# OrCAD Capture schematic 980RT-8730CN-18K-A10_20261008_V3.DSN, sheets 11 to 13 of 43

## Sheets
11 P0031_S3_DUT1: size Custom
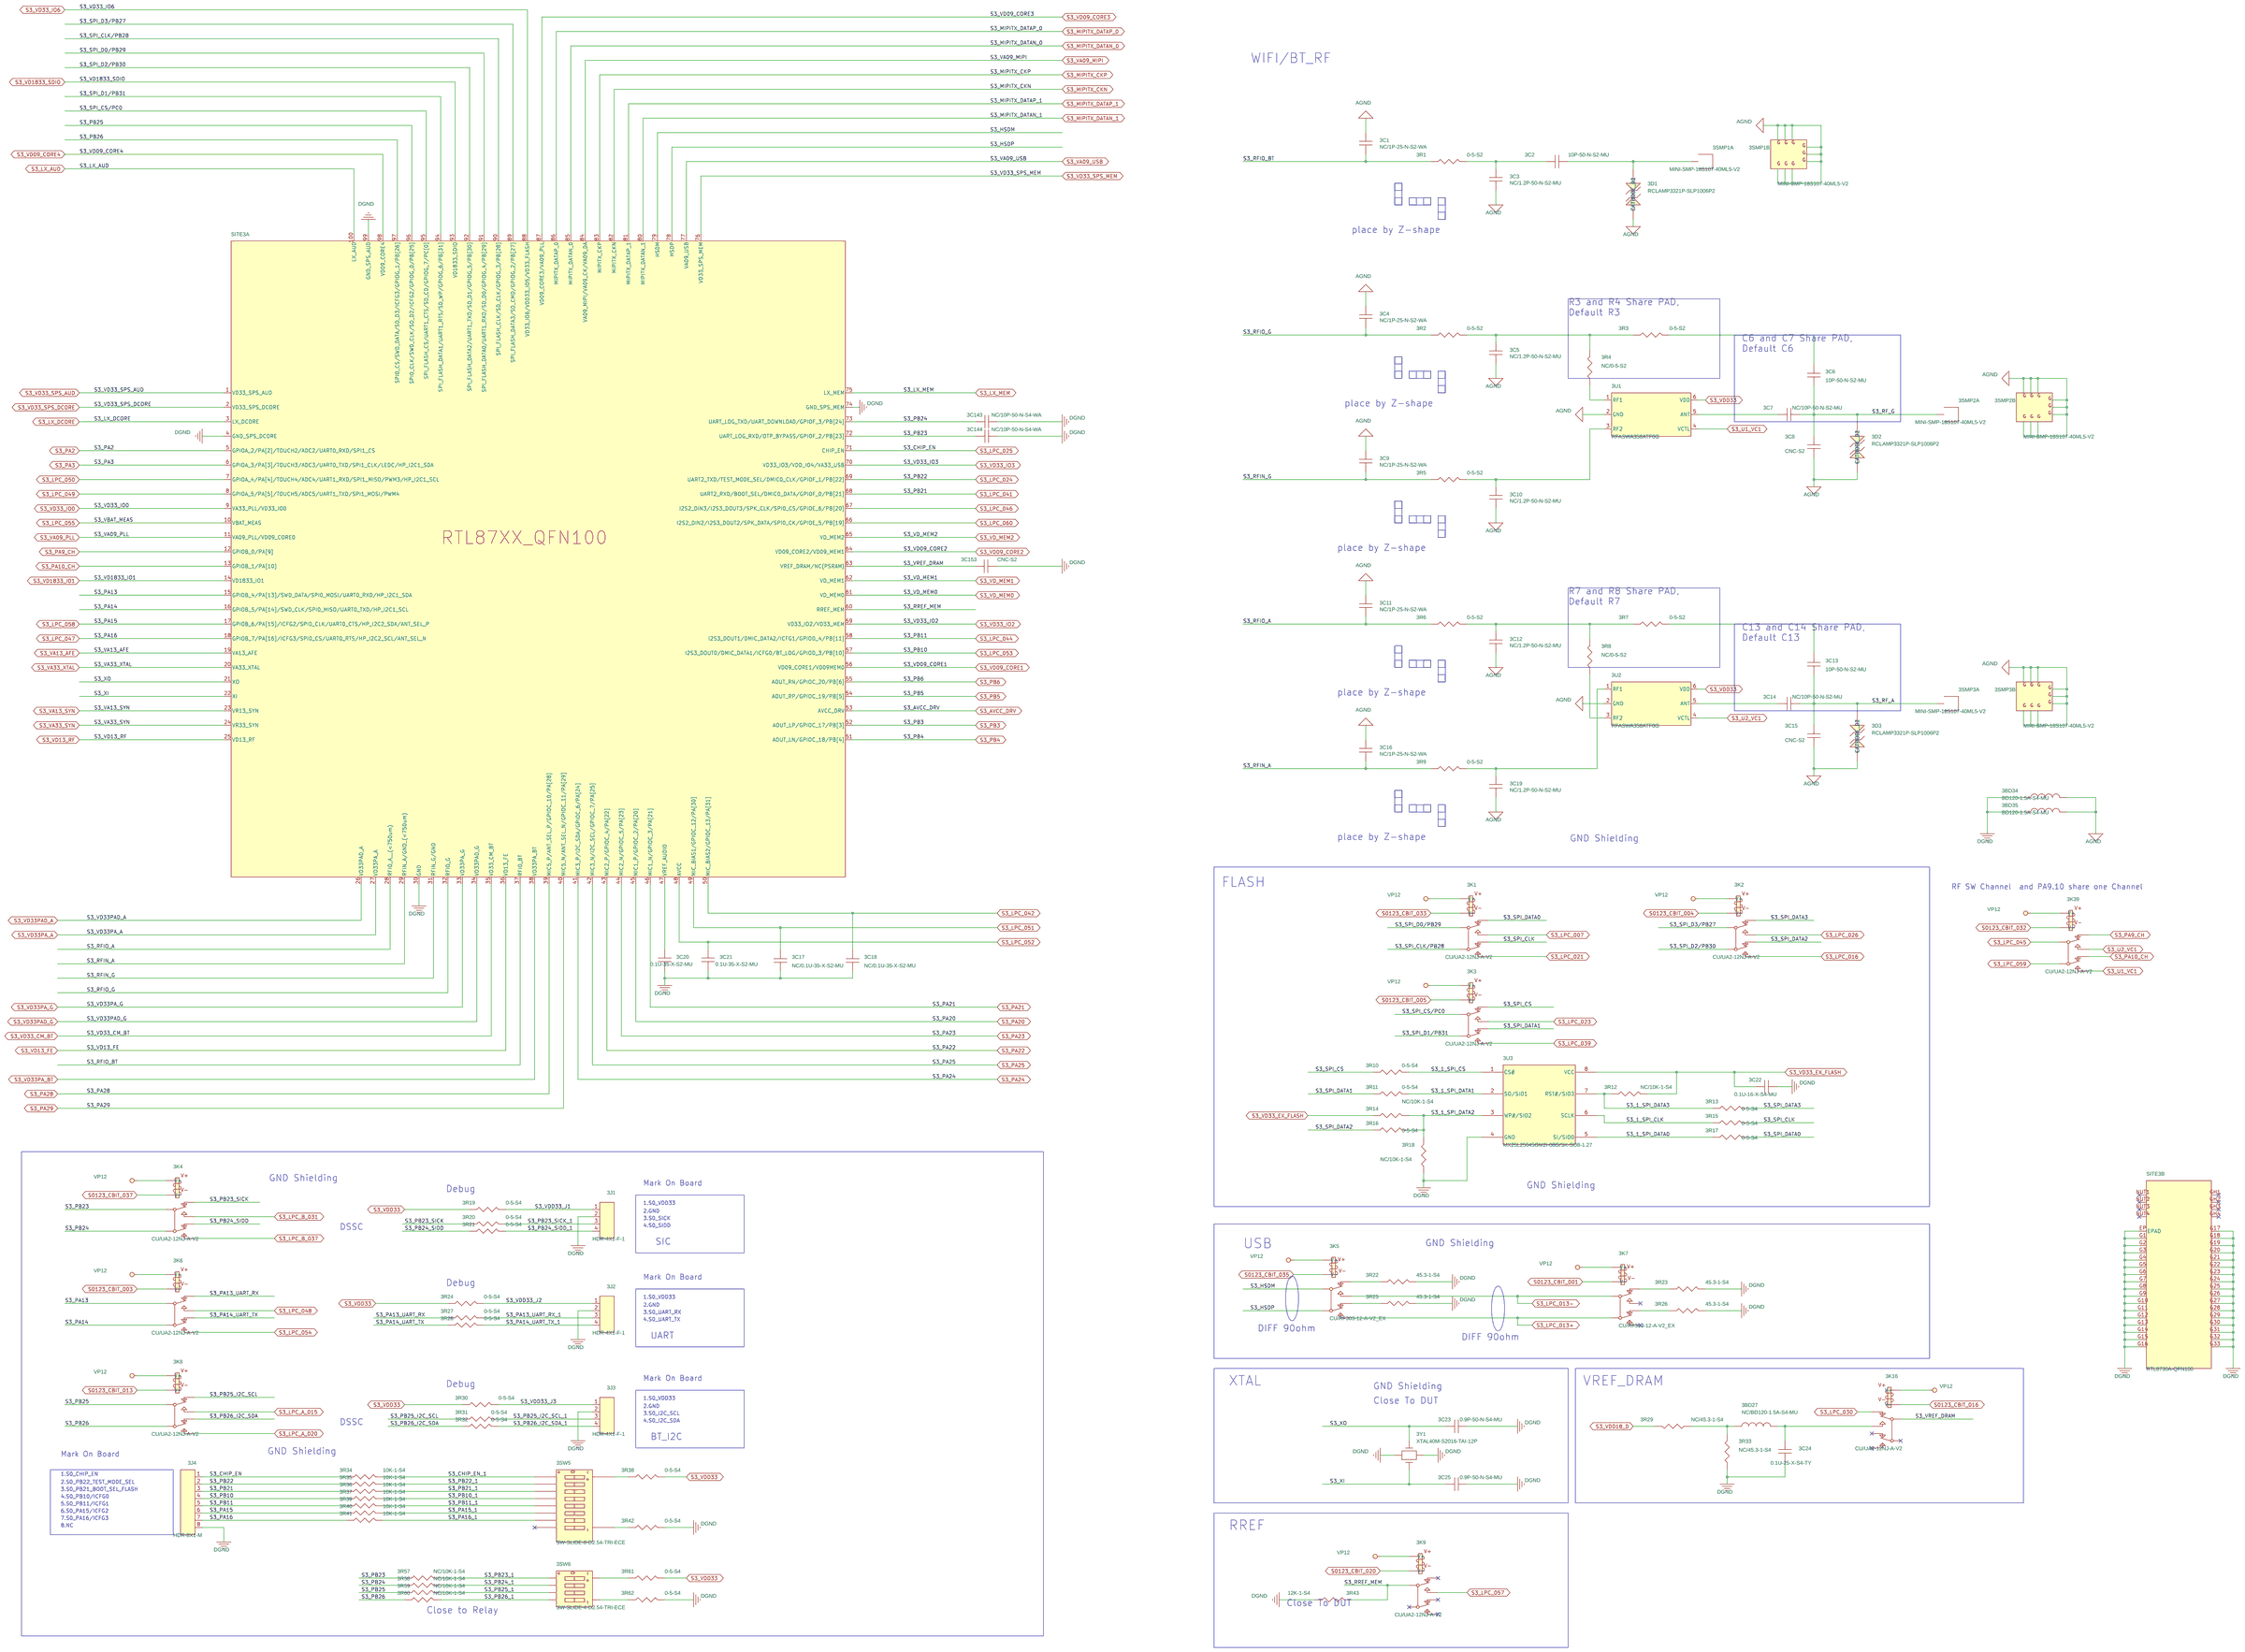
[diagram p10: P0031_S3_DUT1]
12 P0032_S3_Function-test: size A3
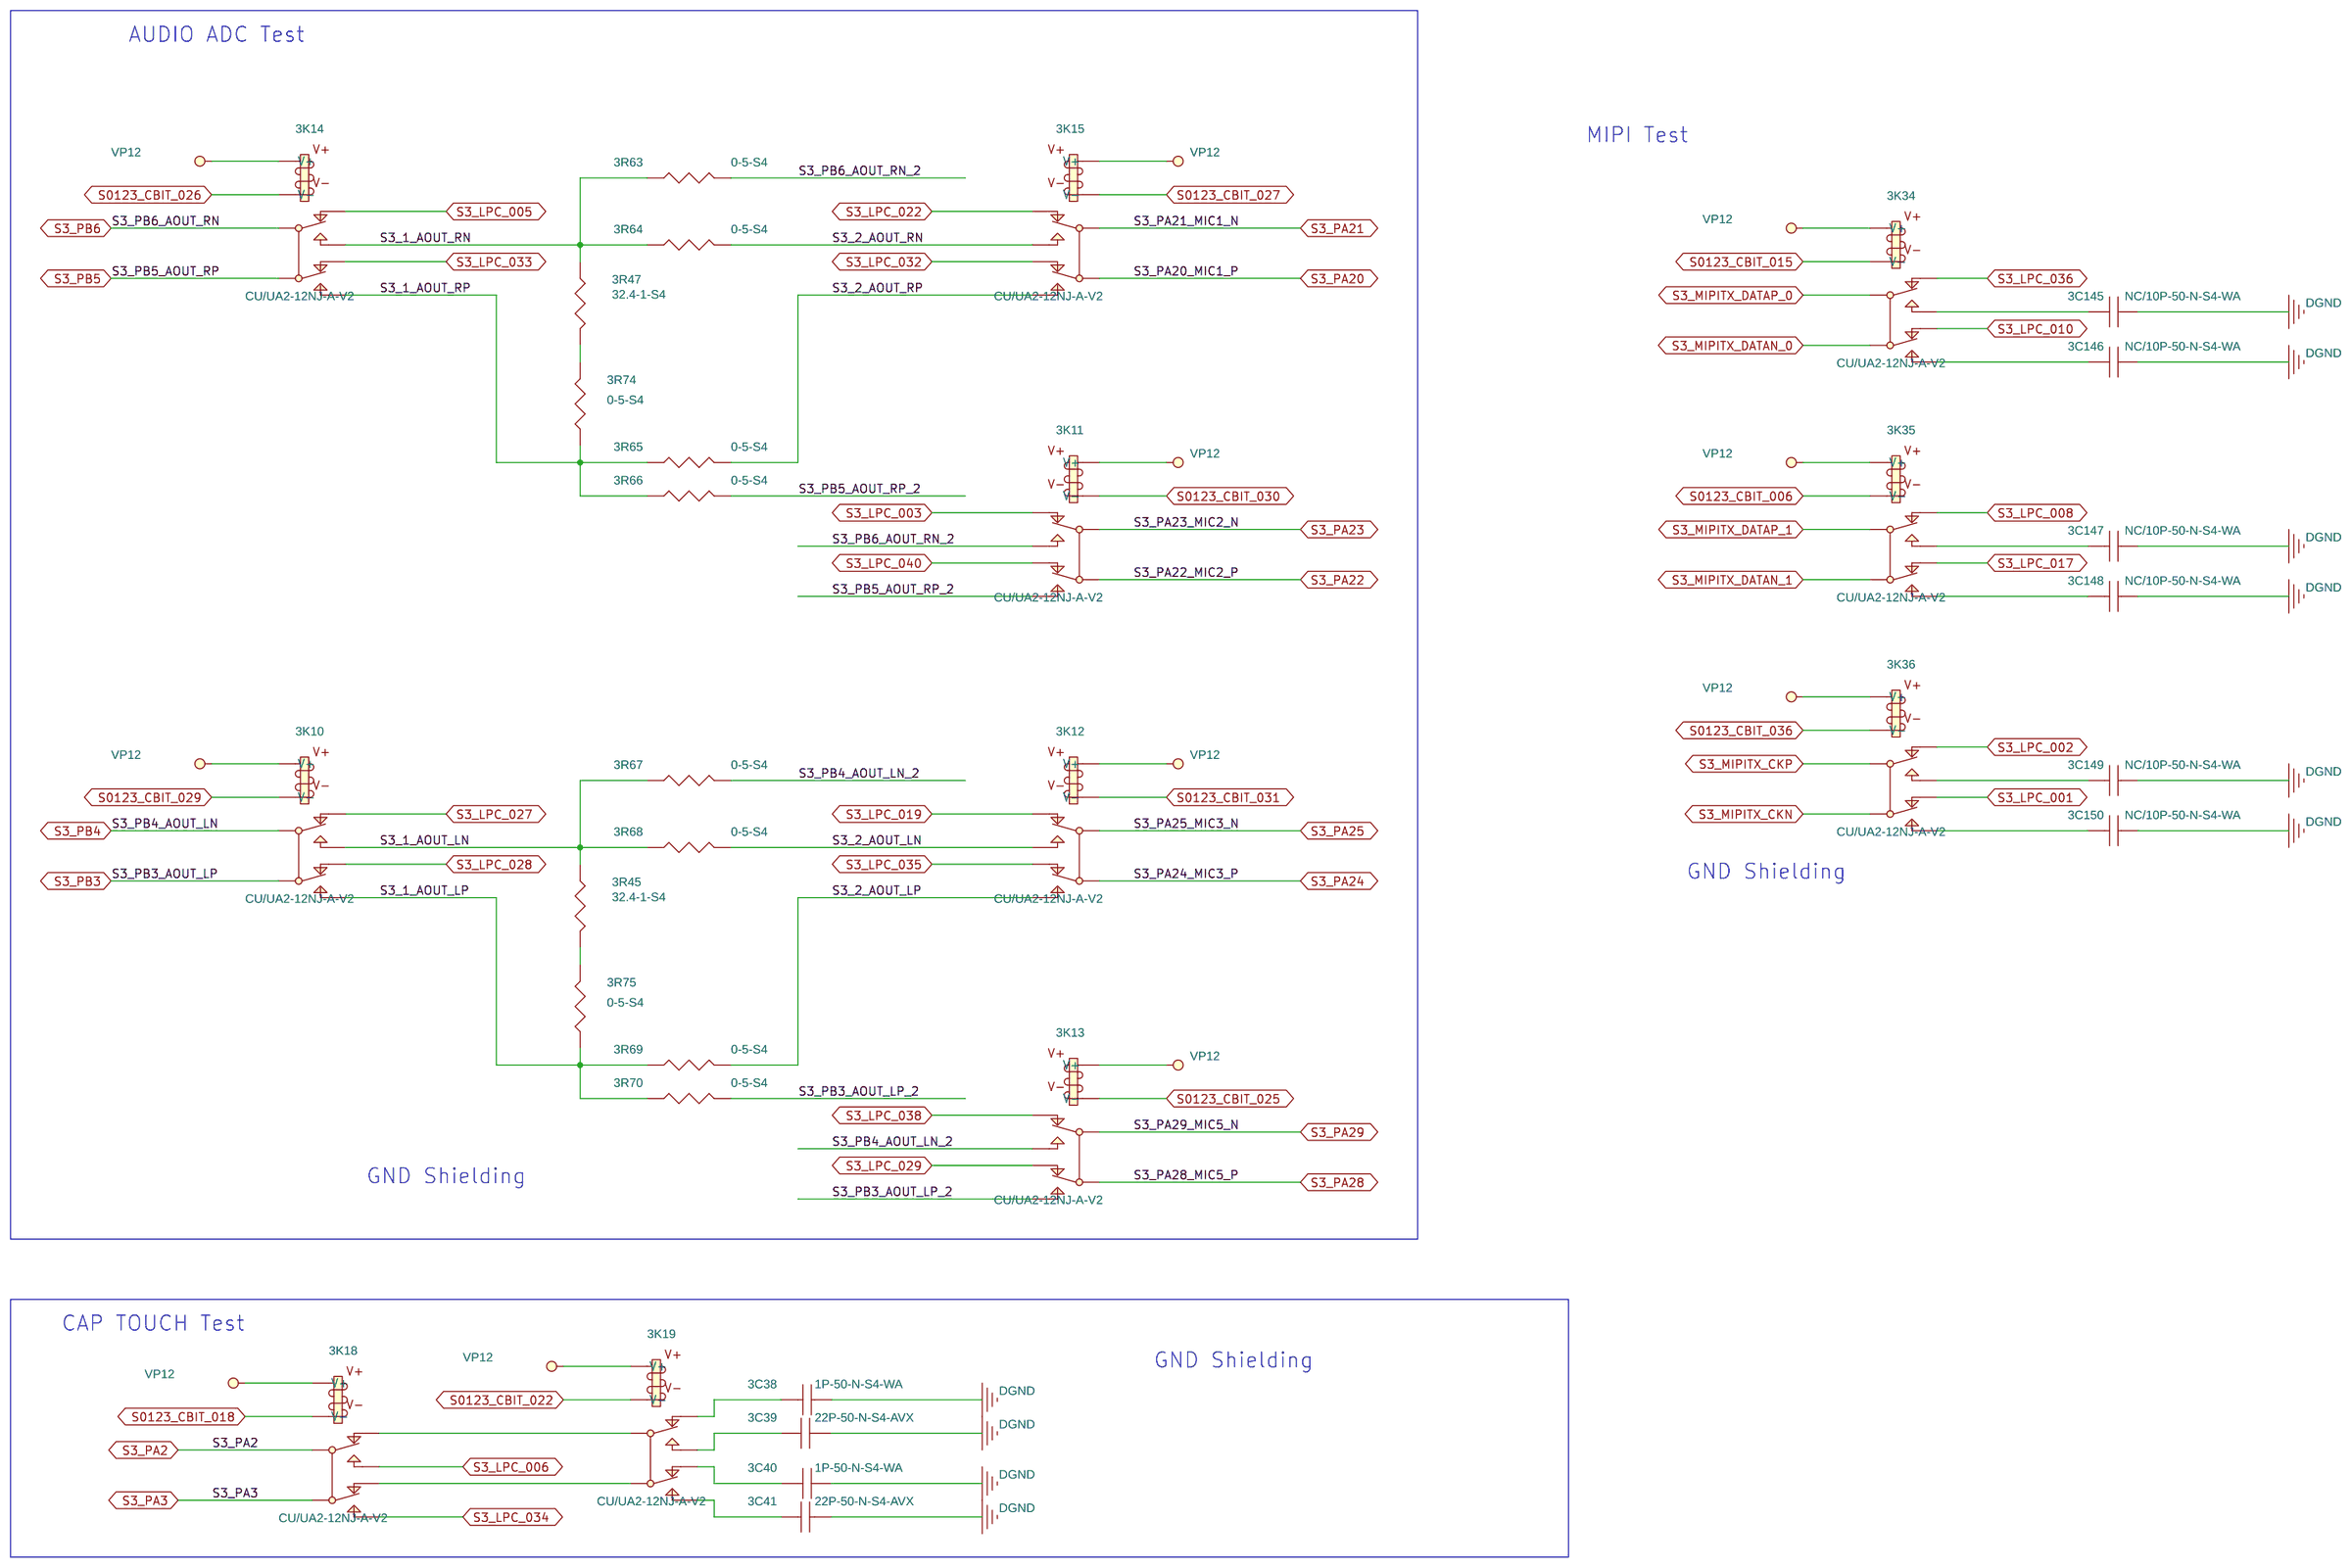
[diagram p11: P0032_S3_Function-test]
13 P0033_S3_Power: size A1
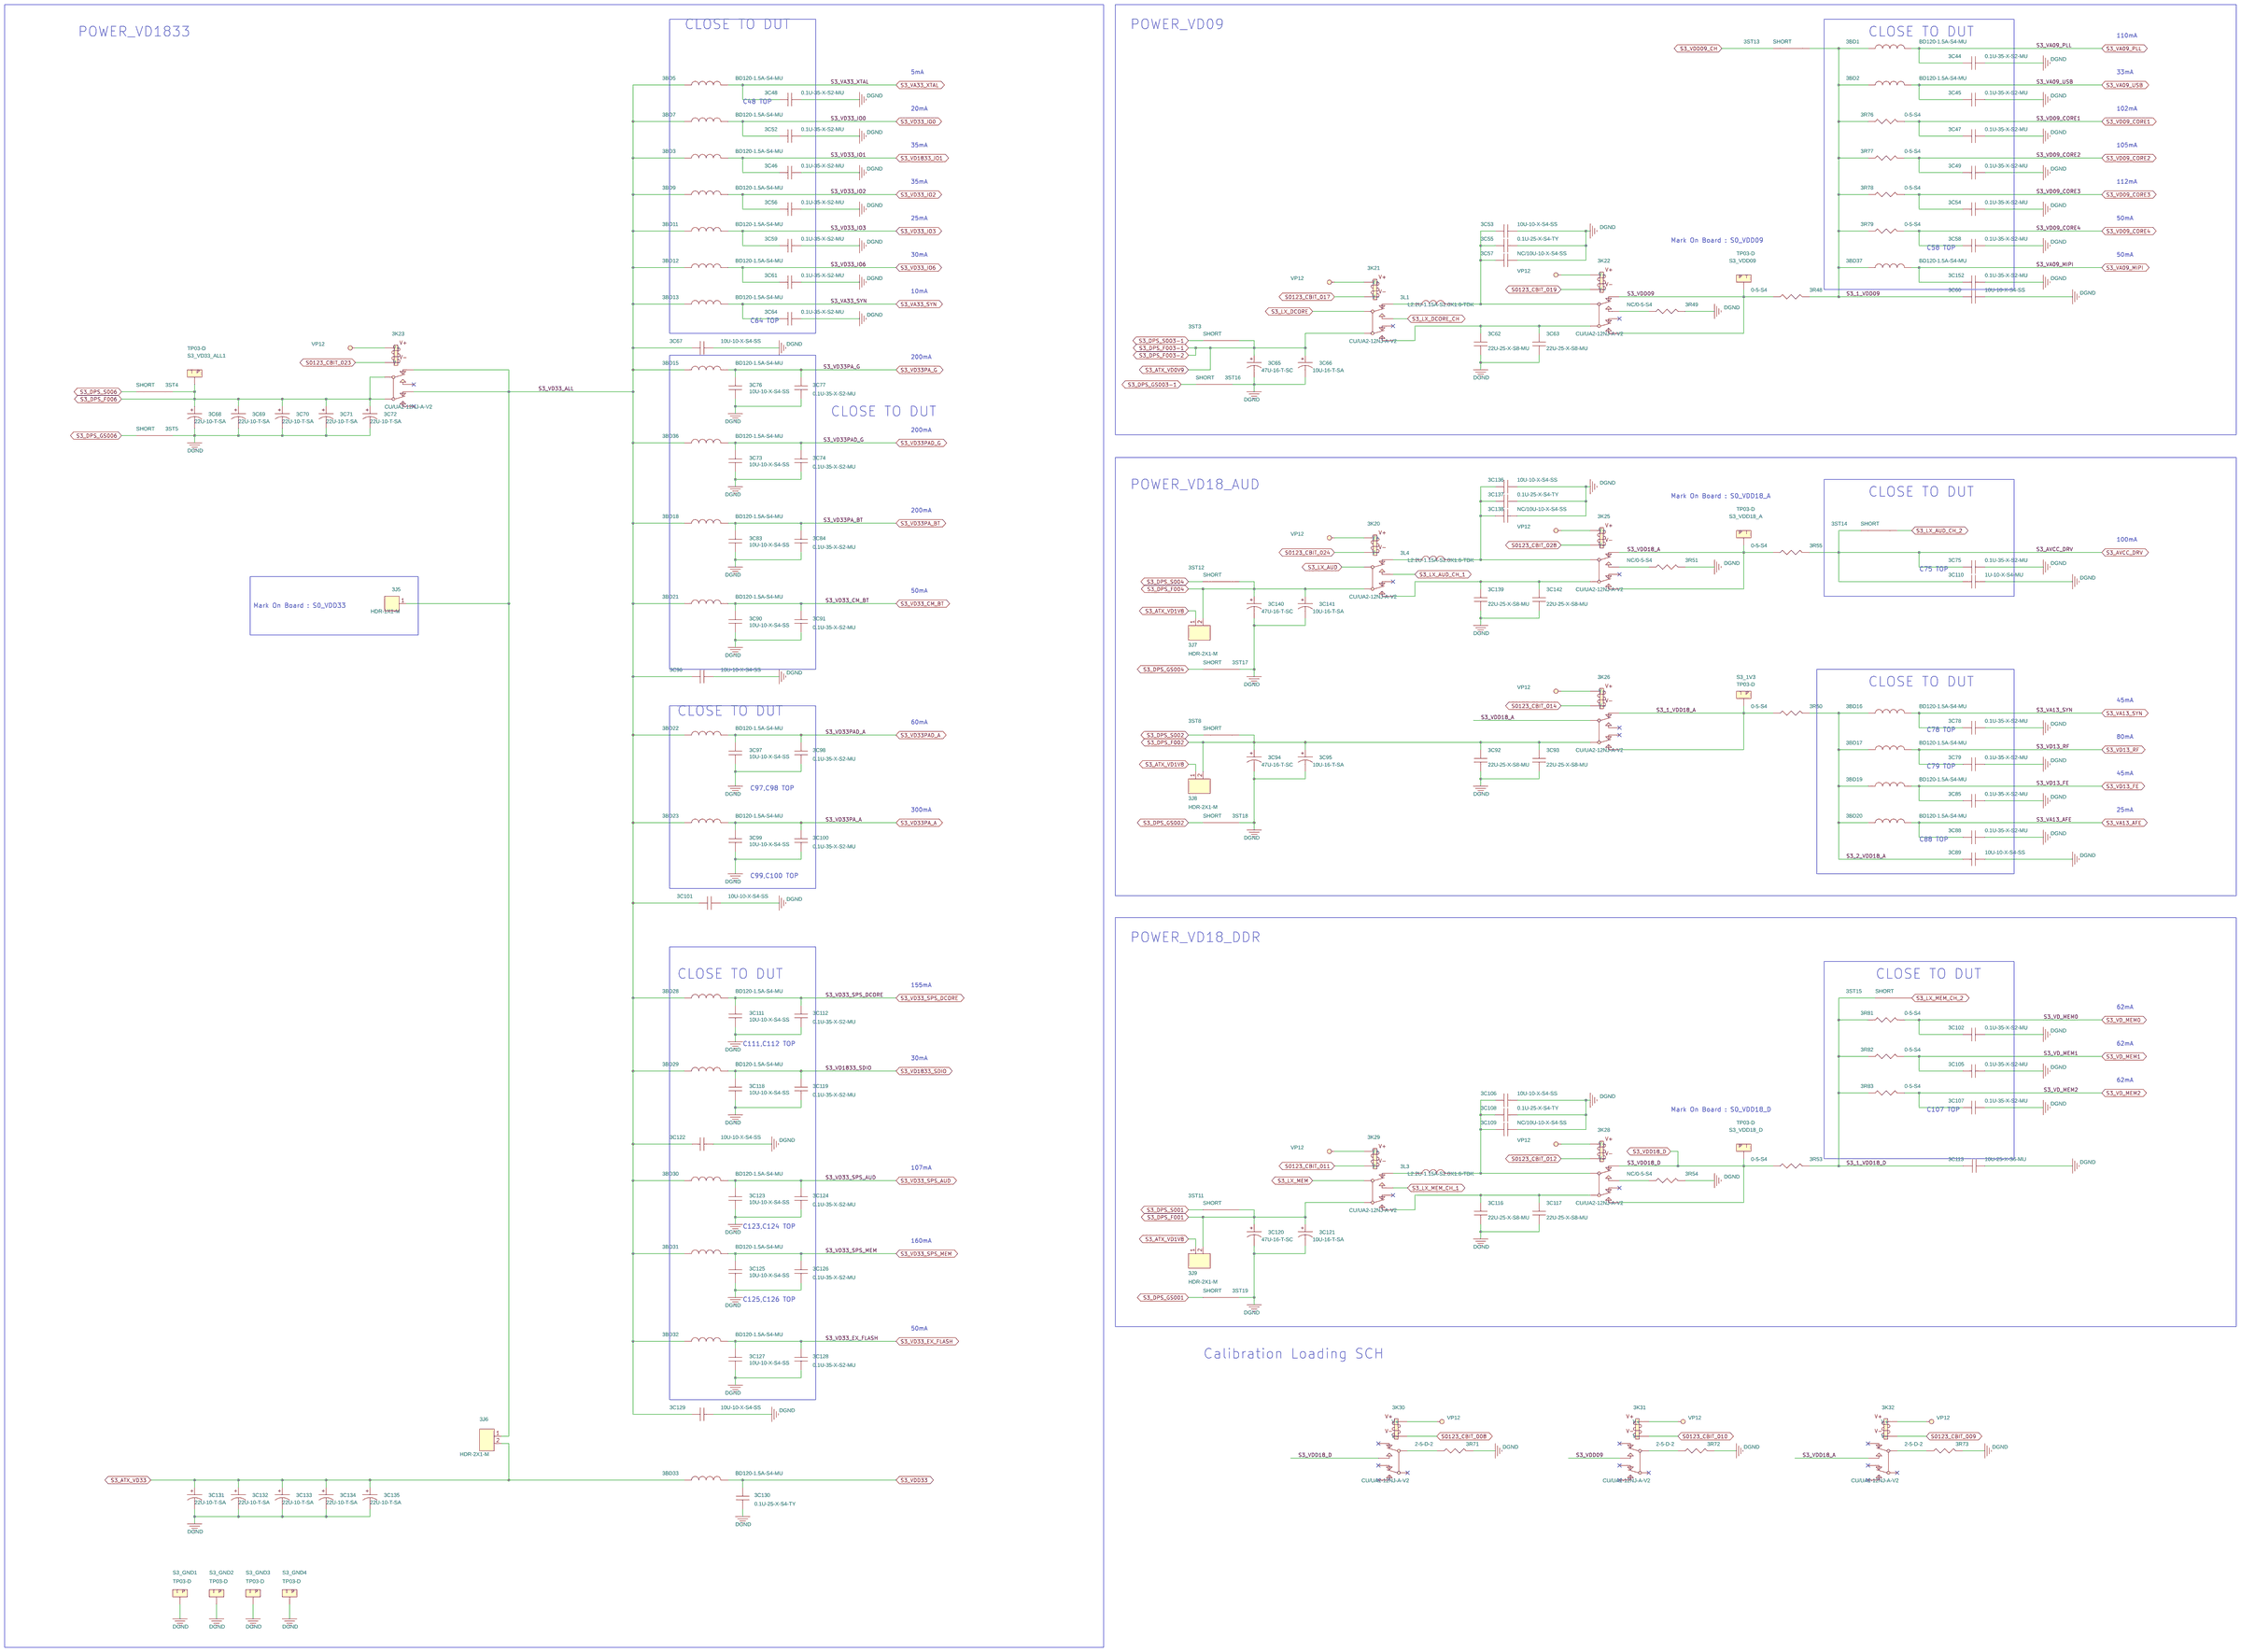
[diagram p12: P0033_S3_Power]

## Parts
sheet P0031_S3_DUT1
3BD27  NC/BD120-1.5A-S4-MU  [FB0402]
3BD34  BD120-1.5A-S4-MU  [FB0402]
3BD35  BD120-1.5A-S4-MU  [FB0402]
3C1  NC/1P-25-N-S2-WA  [C0201]
3C2  10P-50-N-S2-MU  [C0201]
3C3  NC/1.2P-50-N-S2-MU  [C0201]
3C4  NC/1P-25-N-S2-WA  [C0201]
3C5  NC/1.2P-50-N-S2-MU  [C0201]
3C6  10P-50-N-S2-MU  [C0201]
3C7  NC/10P-50-N-S2-MU  [C0201]
3C8  CNC-S2  [C0201]
3C9  NC/1P-25-N-S2-WA  [C0201]
3C10  NC/1.2P-50-N-S2-MU  [C0201]
3C11  NC/1P-25-N-S2-WA  [C0201]
3C12  NC/1.2P-50-N-S2-MU  [C0201]
3C13  10P-50-N-S2-MU  [C0201]
3C14  NC/10P-50-N-S2-MU  [C0201]
3C15  CNC-S2  [C0201]
3C16  NC/1P-25-N-S2-WA  [C0201]
3C17  NC/0.1U-35-X-S2-MU  [C0201]
3C18  NC/0.1U-35-X-S2-MU  [C0201]
3C19  NC/1.2P-50-N-S2-MU  [C0201]
3C20  0.1U-35-X-S2-MU  [C0201]
3C21  0.1U-35-X-S2-MU  [C0201]
3C22  0.1U-16-X-S4-MU  [C0402]
3C23  0.9P-50-N-S4-MU  [C0402]
3C24  0.1U-25-X-S4-TY  [C0402]
3C25  0.9P-50-N-S4-MU  [C0402]
3C143  NC/10P-50-N-S4-WA  [C0402]
3C144  NC/10P-50-N-S4-WA  [C0402]
3C153  CNC-S2  [C0201]
3D1  RCLAMP3321P-SLP1006P2  [DIODE_1X0P6MM]
3D2  RCLAMP3321P-SLP1006P2  [DIODE_1X0P6MM]
3D3  RCLAMP3321P-SLP1006P2  [DIODE_1X0P6MM]
3J1  HDR-4X1-F-1  [CONN_4X1_2P54MM_FL10P5MM]
3J2  HDR-4X1-F-1  [CONN_4X1_2P54MM_FL10P5MM]
3J3  HDR-4X1-F-1  [CONN_4X1_2P54MM_FL10P5MM]
3J4  HDR-8X1-M  [JP_8P_100]
3K1  CU/UA2-12NJ-A-V2  [RL_NECUA2_12V_V2]
3K2  CU/UA2-12NJ-A-V2  [RL_NECUA2_12V_V2]
3K3  CU/UA2-12NJ-A-V2  [RL_NECUA2_12V_V2]
3K4  CU/UA2-12NJ-A-V2  [RL_NECUA2_12V_V2]
3K5  CU/RF303-12-A-V2_EX  [RL_RF303_12V_V2]
3K6  CU/UA2-12NJ-A-V2  [RL_NECUA2_12V_V2]
3K7  CU/RF303-12-A-V2_EX  [RL_RF303_12V_V2]
3K8  CU/UA2-12NJ-A-V2  [RL_NECUA2_12V_V2]
3K9  CU/UA2-12NJ-A-V2  [RL_NECUA2_12V_V2]
3K16  CU/UA2-12NJ-A-V2  [RL_NECUA2_12V_V2]
3K39  CU/UA2-12NJ-A-V2  [RL_NECUA2_12V_V2]
3R1  0-5-S2  [R0201]
3R2  0-5-S2  [R0201]
3R3  0-5-S2  [R0201]
3R4  NC/0-5-S2  [R0201]
3R5  0-5-S2  [R0201]
3R6  0-5-S2  [R0201]
3R7  0-5-S2  [R0201]
3R8  NC/0-5-S2  [R0201]
3R9  0-5-S2  [R0201]
3R10  0-5-S4  [R0402]
3R11  0-5-S4  [R0402]
3R12  NC/10K-1-S4  [R0402]
3R13  0-5-S4  [R0402]
3R14  NC/10K-1-S4  [R0402]
3R15  0-5-S4  [R0402]
3R16  0-5-S4  [R0402]
3R17  0-5-S4  [R0402]
3R18  NC/10K-1-S4  [R0402]
3R19  0-5-S4  [R0402]
3R20  0-5-S4  [R0402]
3R21  0-5-S4  [R0402]
3R22  45.3-1-S4  [R0402]
3R23  45.3-1-S4  [R0402]
3R24  0-5-S4  [R0402]
3R25  45.3-1-S4  [R0402]
3R26  45.3-1-S4  [R0402]
3R27  0-5-S4  [R0402]
3R28  0-5-S4  [R0402]
3R29  NC/45.3-1-S4  [R0402]
3R30  0-5-S4  [R0402]
3R31  0-5-S4  [R0402]
3R32  0-5-S4  [R0402]
3R33  NC/45.3-1-S4  [R0402]
3R34  10K-1-S4  [R0402]
3R35  10K-1-S4  [R0402]
3R36  10K-1-S4  [R0402]
3R37  10K-1-S4  [R0402]
3R38  0-5-S4  [R0402]
3R39  10K-1-S4  [R0402]
3R40  10K-1-S4  [R0402]
3R41  10K-1-S4  [R0402]
3R42  0-5-S4  [R0402]
3R43  12K-1-S4  [R0402]
3R57  NC/10K-1-S4  [R0402]
3R58  NC/10K-1-S4  [R0402]
3R59  NC/10K-1-S4  [R0402]
3R60  NC/10K-1-S4  [R0402]
3R61  0-5-S4  [R0402]
3R62  0-5-S4  [R0402]
3SMP1  MINI-SMP-18S107-40ML5-V2  [CONN_SMP_18S107]  (sections A,B)
3SMP2  MINI-SMP-18S107-40ML5-V2  [CONN_SMP_18S107]  (sections A,B)
3SMP3  MINI-SMP-18S107-40ML5-V2  [CONN_SMP_18S107]  (sections A,B)
3SW5  SW-SLIDE-8-D2.54-TRI-ECE  [SW_DIPX8P_2P54_MM_V2]
3SW6  SW-SLIDE-4-D2.54-TRI-ECE  [SW_DIPX4P_2P54MM_ETD]
3U1  RFASWA358ATF0G  [RF_SW_GW2159_6P]
3U2  RFASWA358ATF0G  [RF_SW_GW2159_6P]
3U3  MX25L25645GM2I-08G/SK-SO8-1.27  [SK_SO8_1P27MM_LOTES]
3Y1  XTAL40M-S2016-TAI-12P  [XTAL_2X1P6MM_4P_0P8MM]
SITE3  RTL8730A-QFN100  [SK_QFN100P_0P35MM_MJC_L8730A]  (sections A,B)
sheet P0032_S3_Function-test
3C38  1P-50-N-S4-WA  [C0402]
3C39  22P-50-N-S4-AVX  [C0402]
3C40  1P-50-N-S4-WA  [C0402]
3C41  22P-50-N-S4-AVX  [C0402]
3C145  NC/10P-50-N-S4-WA  [C0402]
3C146  NC/10P-50-N-S4-WA  [C0402]
3C147  NC/10P-50-N-S4-WA  [C0402]
3C148  NC/10P-50-N-S4-WA  [C0402]
3C149  NC/10P-50-N-S4-WA  [C0402]
3C150  NC/10P-50-N-S4-WA  [C0402]
3K10  CU/UA2-12NJ-A-V2  [RL_NECUA2_12V_V2]
3K11  CU/UA2-12NJ-A-V2  [RL_NECUA2_12V_V2]
3K12  CU/UA2-12NJ-A-V2  [RL_NECUA2_12V_V2]
3K13  CU/UA2-12NJ-A-V2  [RL_NECUA2_12V_V2]
3K14  CU/UA2-12NJ-A-V2  [RL_NECUA2_12V_V2]
3K15  CU/UA2-12NJ-A-V2  [RL_NECUA2_12V_V2]
3K18  CU/UA2-12NJ-A-V2  [RL_NECUA2_12V_V2]
3K19  CU/UA2-12NJ-A-V2  [RL_NECUA2_12V_V2]
3K34  CU/UA2-12NJ-A-V2  [RL_NECUA2_12V_V2]
3K35  CU/UA2-12NJ-A-V2  [RL_NECUA2_12V_V2]
3K36  CU/UA2-12NJ-A-V2  [RL_NECUA2_12V_V2]
3R45  32.4-1-S4  [R0402]
3R47  32.4-1-S4  [R0402]
3R63  0-5-S4  [R0402]
3R64  0-5-S4  [R0402]
3R65  0-5-S4  [R0402]
3R66  0-5-S4  [R0402]
3R67  0-5-S4  [R0402]
3R68  0-5-S4  [R0402]
3R69  0-5-S4  [R0402]
3R70  0-5-S4  [R0402]
3R74  0-5-S4  [R0402]
3R75  0-5-S4  [R0402]
sheet P0033_S3_Power
3BD1  BD120-1.5A-S4-MU  [FB0402]
3BD2  BD120-1.5A-S4-MU  [FB0402]
3BD3  BD120-1.5A-S4-MU  [FB0402]
3BD5  BD120-1.5A-S4-MU  [FB0402]
3BD7  BD120-1.5A-S4-MU  [FB0402]
3BD9  BD120-1.5A-S4-MU  [FB0402]
3BD11  BD120-1.5A-S4-MU  [FB0402]
3BD12  BD120-1.5A-S4-MU  [FB0402]
3BD13  BD120-1.5A-S4-MU  [FB0402]
3BD15  BD120-1.5A-S4-MU  [FB0402]
3BD16  BD120-1.5A-S4-MU  [FB0402]
3BD17  BD120-1.5A-S4-MU  [FB0402]
3BD18  BD120-1.5A-S4-MU  [FB0402]
3BD19  BD120-1.5A-S4-MU  [FB0402]
3BD20  BD120-1.5A-S4-MU  [FB0402]
3BD21  BD120-1.5A-S4-MU  [FB0402]
3BD22  BD120-1.5A-S4-MU  [FB0402]
3BD23  BD120-1.5A-S4-MU  [FB0402]
3BD28  BD120-1.5A-S4-MU  [FB0402]
3BD29  BD120-1.5A-S4-MU  [FB0402]
3BD30  BD120-1.5A-S4-MU  [FB0402]
3BD31  BD120-1.5A-S4-MU  [FB0402]
3BD32  BD120-1.5A-S4-MU  [FB0402]
3BD33  BD120-1.5A-S4-MU  [FB0402]
3BD36  BD120-1.5A-S4-MU  [FB0402]
3BD37  BD120-1.5A-S4-MU  [FB0402]
3C44  0.1U-35-X-S2-MU  [C0201]
3C45  0.1U-35-X-S2-MU  [C0201]
3C46  0.1U-35-X-S2-MU  [C0201]
3C47  0.1U-35-X-S2-MU  [C0201]
3C48  0.1U-35-X-S2-MU  [C0201]
3C49  0.1U-35-X-S2-MU  [C0201]
3C52  0.1U-35-X-S2-MU  [C0201]
3C53  10U-10-X-S4-SS  [C0402]
3C54  0.1U-35-X-S2-MU  [C0201]
3C55  0.1U-25-X-S4-TY  [C0402]
3C56  0.1U-35-X-S2-MU  [C0201]
3C57  NC/10U-10-X-S4-SS  [C0402]
3C58  0.1U-35-X-S2-MU  [C0201]
3C59  0.1U-35-X-S2-MU  [C0201]
3C60  10U-10-X-S4-SS  [C0402]
3C61  0.1U-35-X-S2-MU  [C0201]
3C62  22U-25-X-S8-MU  [C0805]
3C63  22U-25-X-S8-MU  [C0805]
3C64  0.1U-35-X-S2-MU  [C0201]
3C65  47U-16-T-SC  [CODE_C]
3C66  10U-16-T-SA  [CODE_A]
3C67  10U-10-X-S4-SS  [C0402]
3C68  22U-10-T-SA  [CODE_A]
3C69  22U-10-T-SA  [CODE_A]
3C70  22U-10-T-SA  [CODE_A]
3C71  22U-10-T-SA  [CODE_A]
3C72  22U-10-T-SA  [CODE_A]
3C73  10U-10-X-S4-SS  [C0402]
3C74  0.1U-35-X-S2-MU  [C0201]
3C75  0.1U-35-X-S2-MU  [C0201]
3C76  10U-10-X-S4-SS  [C0402]
3C77  0.1U-35-X-S2-MU  [C0201]
3C78  0.1U-35-X-S2-MU  [C0201]
3C79  0.1U-35-X-S2-MU  [C0201]
3C83  10U-10-X-S4-SS  [C0402]
3C84  0.1U-35-X-S2-MU  [C0201]
3C85  0.1U-35-X-S2-MU  [C0201]
3C88  0.1U-35-X-S2-MU  [C0201]
3C89  10U-10-X-S4-SS  [C0402]
3C90  10U-10-X-S4-SS  [C0402]
3C91  0.1U-35-X-S2-MU  [C0201]
3C92  22U-25-X-S8-MU  [C0805]
3C93  22U-25-X-S8-MU  [C0805]
3C94  47U-16-T-SC  [CODE_C]
3C95  10U-16-T-SA  [CODE_A]
3C96  10U-10-X-S4-SS  [C0402]
3C97  10U-10-X-S4-SS  [C0402]
3C98  0.1U-35-X-S2-MU  [C0201]
3C99  10U-10-X-S4-SS  [C0402]
3C100  0.1U-35-X-S2-MU  [C0201]
3C101  10U-10-X-S4-SS  [C0402]
3C102  0.1U-35-X-S2-MU  [C0201]
3C105  0.1U-35-X-S2-MU  [C0201]
3C106  10U-10-X-S4-SS  [C0402]
3C107  0.1U-35-X-S2-MU  [C0201]
3C108  0.1U-25-X-S4-TY  [C0402]
3C109  NC/10U-10-X-S4-SS  [C0402]
3C110  1U-10-X-S4-MU  [C0402]
3C111  10U-10-X-S4-SS  [C0402]
3C112  0.1U-35-X-S2-MU  [C0201]
3C113  10U-25-X-S6-MU  [C0603]
3C116  22U-25-X-S8-MU  [C0805]
3C117  22U-25-X-S8-MU  [C0805]
3C118  10U-10-X-S4-SS  [C0402]
3C119  0.1U-35-X-S2-MU  [C0201]
3C120  47U-16-T-SC  [CODE_C]
3C121  10U-16-T-SA  [CODE_A]
3C122  10U-10-X-S4-SS  [C0402]
3C123  10U-10-X-S4-SS  [C0402]
3C124  0.1U-35-X-S2-MU  [C0201]
3C125  10U-10-X-S4-SS  [C0402]
3C126  0.1U-35-X-S2-MU  [C0201]
3C127  10U-10-X-S4-SS  [C0402]
3C128  0.1U-35-X-S2-MU  [C0201]
3C129  10U-10-X-S4-SS  [C0402]
3C130  0.1U-25-X-S4-TY  [C0402]
3C131  22U-10-T-SA  [CODE_A]
3C132  22U-10-T-SA  [CODE_A]
3C133  22U-10-T-SA  [CODE_A]
3C134  22U-10-T-SA  [CODE_A]
3C135  22U-10-T-SA  [CODE_A]
3C136  10U-10-X-S4-SS  [C0402]
3C137  0.1U-25-X-S4-TY  [C0402]
3C138  NC/10U-10-X-S4-SS  [C0402]
3C139  22U-25-X-S8-MU  [C0805]
3C140  47U-16-T-SC  [CODE_C]
3C141  10U-16-T-SA  [CODE_A]
3C142  22U-25-X-S8-MU  [C0805]
3C152  0.1U-35-X-S2-MU  [C0201]
3J5  HDR-1X1-M  [JP_1P_RD070_040]
3J6  HDR-2X1-M  [JP_2P_100]
3J7  HDR-2X1-M  [JP_2P_100]
3J8  HDR-2X1-M  [JP_2P_100]
3J9  HDR-2X1-M  [JP_2P_100]
3K20  CU/UA2-12NJ-A-V2  [RL_NECUA2_12V_V2]
3K21  CU/UA2-12NJ-A-V2  [RL_NECUA2_12V_V2]
3K22  CU/UA2-12NJ-A-V2  [RL_NECUA2_12V_V2]
3K23  CU/UA2-12NJ-A-V2  [RL_NECUA2_12V_V2]
3K25  CU/UA2-12NJ-A-V2  [RL_NECUA2_12V_V2]
3K26  CU/UA2-12NJ-A-V2  [RL_NECUA2_12V_V2]
3K28  CU/UA2-12NJ-A-V2  [RL_NECUA2_12V_V2]
3K29  CU/UA2-12NJ-A-V2  [RL_NECUA2_12V_V2]
3K30  CU/UA2-12NJ-A-V2  [RL_NECUA2_12V_V2]
3K31  CU/UA2-12NJ-A-V2  [RL_NECUA2_12V_V2]
3K32  CU/UA2-12NJ-A-V2  [RL_NECUA2_12V_V2]
3L1  L2.2U-1.15A-S2.0X1.6-TDK  [IND_VL252012E]
3L3  L2.2U-1.15A-S2.0X1.6-TDK  [IND_VL252012E]
3L4  L2.2U-1.15A-S2.0X1.6-TDK  [IND_VL252012E]
3R48  0-5-S4  [R0402]
3R49  NC/0-5-S4  [R0402]
3R50  0-5-S4  [R0402]
3R51  NC/0-5-S4  [R0402]
3R53  0-5-S4  [R0402]
3R54  NC/0-5-S4  [R0402]
3R55  0-5-S4  [R0402]
3R71  2-5-D-2  [RC02W_27MM]
3R72  2-5-D-2  [RC02W_27MM]
3R73  2-5-D-2  [RC02W_27MM]
3R76  0-5-S4  [R0402]
3R77  0-5-S4  [R0402]
3R78  0-5-S4  [R0402]
3R79  0-5-S4  [R0402]
3R81  0-5-S4  [R0402]
3R82  0-5-S4  [R0402]
3R83  0-5-S4  [R0402]
3ST3  SHORT  [DEFAULT_SHORT_SMALL]
3ST4  SHORT  [DEFAULT_SHORT_SMALL]
3ST5  SHORT  [DEFAULT_SHORT_SMALL]
3ST8  SHORT  [DEFAULT_SHORT_SMALL]
3ST11  SHORT  [DEFAULT_SHORT_SMALL]
3ST12  SHORT  [DEFAULT_SHORT_SMALL]
3ST13  SHORT  [DEFAULT_SHORT_SMALL]
3ST14  SHORT  [DEFAULT_SHORT_SMALL]
3ST15  SHORT  [DEFAULT_SHORT_SMALL]
3ST16  SHORT  [DEFAULT_SHORT_SMALL]
3ST17  SHORT  [DEFAULT_SHORT_SMALL]
3ST18  SHORT  [DEFAULT_SHORT_SMALL]
3ST19  SHORT  [DEFAULT_SHORT_SMALL]
S3_1V3  TP03-D  [TP_060_040]
S3_GND1  TP03-D  [TP_060_040]
S3_GND2  TP03-D  [TP_060_040]
S3_GND3  TP03-D  [TP_060_040]
S3_GND4  TP03-D  [TP_060_040]
S3_VD33_ALL1  TP03-D  [TP_060_040]
S3_VDD09  TP03-D  [TP_060_040]
S3_VDD18_A  TP03-D  [TP_060_040]
S3_VDD18_D  TP03-D  [TP_060_040]

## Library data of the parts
3BD27 = BD120-1.5A-S4-MU: KAIROSNAME: BD27
3BD34 = BD120-1.5A-S4-MU: KAIROSNAME: BD34
3BD35 = BD120-1.5A-S4-MU: KAIROSNAME: BD35
3C1 3C4 3C9 3C11 3C16 = 1P-25-N-S2-WA
3C2 3C6 3C7 3C13 3C14 = 10P-50-N-S2-MU
3C3 3C5 3C10 3C12 3C19 = 1.2P-50-N-S2-MU
3C8 3C15 = CNC-S4
3C17 3C18 3C46 = 0.1U-35-X-S2-MU: KAIROSNAME: C46
3C20 3C21 3C98 = 0.1U-35-X-S2-MU: KAIROSNAME: C98
3C22 = 0.1U-16-X-S4: KAIROSNAME: C22
3C23 = 10P-50-N-S4-MU-1: KAIROSNAME: C23
3C24 = 0.1U-25-X-S4-TY: KAIROSNAME: C24
3C25 = 10P-50-N-S4-MU-1: KAIROSNAME: C25
3C143-3C150 = 10P-50-N-S4-WA
3C48 3C153 = 0.1U-35-X-S2-MU: KAIROSNAME: C48
3D1 = RCLAMP3321P-SLP1006P2: KAIROSNAME: D1
3D2 = RCLAMP3321P-SLP1006P2: KAIROSNAME: D2
3D3 = RCLAMP3321P-SLP1006P2: KAIROSNAME: D3
3J1-3J3 = HDR-4X1-F-1
3J4 = HDR-8X1-M: KAIROSNAME: J4
3K1 3K39 = CU_UA2-12NJ-A-V2: KAIROSNAME: K1
3K2 3K16 = CU_UA2-12NJ-A-V2: KAIROSNAME: K2
3K3 = CU_UA2-12NJ-A-V2: KAIROSNAME: K3
3K4 = CU_UA2-12NJ-A-V2: KAIROSNAME: K4
3K5 = CU_RF303-12-A-V2_EX: KAIROSNAME: K5
3K6 = CU_UA2-12NJ-A-V2: KAIROSNAME: K6
3K7 = CU_RF303-12-A-V2_EX: KAIROSNAME: K7
3K8 = CU_UA2-12NJ-A-V2: KAIROSNAME: K8
3K9 = CU_UA2-12NJ-A-V2: KAIROSNAME: K9
3R1-3R9 = 0-5-S2
3R10 = 0-5-S4: KAIROSNAME: R10
3R11 = 0-5-S4: KAIROSNAME: R11
3R12 = 10K-1-S4: KAIROSNAME: R12
3R13 = 0-5-S4: KAIROSNAME: R13
3R14 = 10K-1-S4: KAIROSNAME: R14
3R15 = 0-5-S4: KAIROSNAME: R15
3R16 = 0-5-S4: KAIROSNAME: R16
3R17 = 0-5-S4: KAIROSNAME: R17
3R18 = 10K-1-S4: KAIROSNAME: R18
3R19 = 0-5-S4: KAIROSNAME: R19
3R20 = 0-5-S4: KAIROSNAME: R20
3R21 = 0-5-S4: KAIROSNAME: R21
3R22 = 45.3-1-S4: KAIROSNAME: R22
3R23 = 45.3-1-S4: KAIROSNAME: R23
3R24 = 0-5-S4: KAIROSNAME: R24
3R25 = 45.3-1-S4: KAIROSNAME: R25
3R26 = 45.3-1-S4: KAIROSNAME: R26
3R27 = 0-5-S4: KAIROSNAME: R27
3R28 = 0-5-S4: KAIROSNAME: R28
3R29 = 45.3-1-S4: KAIROSNAME: R29
3R30 = 0-5-S4: KAIROSNAME: R30
3R31 = 0-5-S4: KAIROSNAME: R31
3R32 = 0-5-S4: KAIROSNAME: R32
3R33 = 45.3-1-S4: KAIROSNAME: R33
3R34 = 10K-1-S4: KAIROSNAME: R34
3R35 = 10K-1-S4: KAIROSNAME: R35
3R36 = 10K-1-S4: KAIROSNAME: R36
3R37 = 10K-1-S4: KAIROSNAME: R37
3R38 = 0-5-S4: KAIROSNAME: R38
3R39 = 10K-1-S4: KAIROSNAME: R39
3R40 = 10K-1-S4: KAIROSNAME: R40
3R41 = 10K-1-S4: KAIROSNAME: R41
3R42 = 0-5-S4: KAIROSNAME: R42
3R43 = 12K-1-S4: KAIROSNAME: R43
3R57 = 10K-1-S4: KAIROSNAME: R57
3R58 = 10K-1-S4: KAIROSNAME: R58
3R59 = 10K-1-S4: KAIROSNAME: R59
3R60 = 10K-1-S4: KAIROSNAME: R60
3R61 = 0-5-S4: KAIROSNAME: R61
3R62 = 0-5-S4: KAIROSNAME: R62
3SMP1 = MINI-SMP-18S107-40ML5-V2: KAIROSNAME: SMP1A
3SMP2 = MINI-SMP-18S107-40ML5-V2: KAIROSNAME: SMP2A
3SMP3 = MINI-SMP-18S107-40ML5-V2: KAIROSNAME: SMP3A
3SW5 = SW-SLIDE-8-D2.54-TRI-ECE
3SW6 = SW-SLIDE-4-D2.54-TRI-ECE
3U1 3U2 = RFASWA358ATF0G
3U3 = MX25R6435FM2IL0-SOP8: KAIROSNAME: U3
3Y1 = XTAL40M-S2016-TAI-12P: KAIROSNAME: Y1
SITE3 = RTL8730A-QFN100
3C38 = 10P-50-N-S4-MU-1: KAIROSNAME: C38
3C39 = 33P-50-N-S4-WA: KAIROSNAME: C39
3C40 = 10P-50-N-S4-MU-1: KAIROSNAME: C40
3C41 = 33P-50-N-S4-WA: KAIROSNAME: C41
3K10 = CU_UA2-12NJ-A-V2: KAIROSNAME: K10
3K11 = CU_UA2-12NJ-A-V2: KAIROSNAME: K11
3K12 = CU_UA2-12NJ-A-V2: KAIROSNAME: K12
3K13 = CU_UA2-12NJ-A-V2: KAIROSNAME: K13
3K14 = CU_UA2-12NJ-A-V2: KAIROSNAME: K14
3K15 3K34-3K36 = CU_UA2-12NJ-A-V2: KAIROSNAME: K15
3K18 = CU_UA2-12NJ-A-V2: KAIROSNAME: K18
3K19 = CU_UA2-12NJ-A-V2: KAIROSNAME: K19
3R45 = 32.4-1-S4: KAIROSNAME: R45
3R47 = 32.4-1-S4: KAIROSNAME: R47
3R63 = 0-5-S4: KAIROSNAME: R63
3R64 = 0-5-S4: KAIROSNAME: R64
3R65 3R74 3R75 = 0-5-S4: KAIROSNAME: R65
3R66 = 0-5-S4: KAIROSNAME: R66
3R67 = 0-5-S4: KAIROSNAME: R67
3R68 = 0-5-S4: KAIROSNAME: R68
3R69 = 0-5-S4: KAIROSNAME: R69
3R70 = 0-5-S4: KAIROSNAME: R70
3BD1 = BD120-1.5A-S4-MU: KAIROSNAME: BD1
3BD2 = BD120-1.5A-S4-MU: KAIROSNAME: BD2
3BD3 = BD120-1.5A-S4-MU: KAIROSNAME: BD3
3BD5 = BD120-1.5A-S4-MU: KAIROSNAME: BD5
3BD7 = BD120-1.5A-S4-MU: KAIROSNAME: BD7
3BD9 = BD120-1.5A-S4-MU: KAIROSNAME: BD9
3BD11 = BD120-1.5A-S4-MU: KAIROSNAME: BD11
3BD12 = BD120-1.5A-S4-MU: KAIROSNAME: BD12
3BD13 = BD120-1.5A-S4-MU: KAIROSNAME: BD13
3BD15 3BD36 = BD120-1.5A-S4-MU: KAIROSNAME: BD15
3BD16 = BD120-1.5A-S4-MU: KAIROSNAME: BD16
3BD17 = BD120-1.5A-S4-MU: KAIROSNAME: BD17
3BD18 = BD120-1.5A-S4-MU: KAIROSNAME: BD18
3BD19 = BD120-1.5A-S4-MU: KAIROSNAME: BD19
3BD20 = BD120-1.5A-S4-MU: KAIROSNAME: BD20
3BD21 = BD120-1.5A-S4-MU: KAIROSNAME: BD21
3BD22 = BD120-1.5A-S4-MU: KAIROSNAME: BD22
3BD23 = BD120-1.5A-S4-MU: KAIROSNAME: BD23
3BD28 = BD120-1.5A-S4-MU: KAIROSNAME: BD28
3BD29 = BD120-1.5A-S4-MU: KAIROSNAME: BD29
3BD30 = BD120-1.5A-S4-MU: KAIROSNAME: BD30
3BD31 = BD120-1.5A-S4-MU: KAIROSNAME: BD31
3BD32 = BD120-1.5A-S4-MU: KAIROSNAME: BD32
3BD33 = BD120-1.5A-S4-MU: KAIROSNAME: BD33
3BD37 = BD120-1.5A-S4-MU: KAIROSNAME: BD10
3C44 = 0.1U-35-X-S2-MU: KAIROSNAME: C44
3C45 = 0.1U-35-X-S2-MU: KAIROSNAME: C45
3C47 = 0.1U-35-X-S2-MU: KAIROSNAME: C47
3C49 = 0.1U-35-X-S2-MU: KAIROSNAME: C49
3C52 = 0.1U-35-X-S2-MU: KAIROSNAME: C52
3C53 = 10U-10-X-S4-SS: KAIROSNAME: C53
3C54 = 0.1U-35-X-S2-MU: KAIROSNAME: C54
3C55 = 0.1U-25-X-S4-TY: KAIROSNAME: C55
3C56 = 0.1U-35-X-S2-MU: KAIROSNAME: C56
3C57 = 10U-10-X-S4-SS: KAIROSNAME: C57
3C58 3C152 = 0.1U-35-X-S2-MU: KAIROSNAME: C58
3C59 = 0.1U-35-X-S2-MU: KAIROSNAME: C59
3C60 = 10U-10-X-S4-SS: KAIROSNAME: C60
3C61 = 0.1U-35-X-S2-MU: KAIROSNAME: C61
3C62 = 22U-25-X-S8-MU: KAIROSNAME: C62
3C63 = 22U-25-X-S8-MU: KAIROSNAME: C63
3C64 = 0.1U-35-X-S2-MU: KAIROSNAME: C64
3C65 = 47U-16-T-SC: KAIROSNAME: C65
3C66 = 10U-16-T-SA: KAIROSNAME: C66
3C67 = 10U-10-X-S4-SS: KAIROSNAME: C67
3C68 = 22U-10-T-SA: KAIROSNAME: C68
3C69 = 22U-10-T-SA: KAIROSNAME: C69
3C70 = 22U-10-T-SA: KAIROSNAME: C70
3C71 = 22U-10-T-SA: KAIROSNAME: C71
3C72 = 22U-10-T-SA: KAIROSNAME: C72
3C73 3C76 = 10U-10-X-S4-SS: KAIROSNAME: C76
3C74 3C77 = 0.1U-35-X-S2-MU: KAIROSNAME: C77
3C75 = 0.1U-35-X-S2-MU: KAIROSNAME: C75
3C78 = 0.1U-35-X-S2-MU: KAIROSNAME: C78
3C79 = 0.1U-35-X-S2-MU: KAIROSNAME: C79
3C83 = 10U-10-X-S4-SS: KAIROSNAME: C83
3C84 = 0.1U-35-X-S2-MU: KAIROSNAME: C84
3C85 = 0.1U-35-X-S2-MU: KAIROSNAME: C85
3C88 = 0.1U-35-X-S2-MU: KAIROSNAME: C88
3C89 = 10U-10-X-S4-SS: KAIROSNAME: C89
3C90 = 10U-10-X-S4-SS: KAIROSNAME: C90
3C91 = 0.1U-35-X-S2-MU: KAIROSNAME: C91
3C92 = 22U-25-X-S8-MU: KAIROSNAME: C92
3C93 = 22U-25-X-S8-MU: KAIROSNAME: C93
3C94 = 47U-16-T-SC: KAIROSNAME: C94
3C95 = 10U-16-T-SA: KAIROSNAME: C95
3C96 = 10U-10-X-S4-SS: KAIROSNAME: C96
3C97 = 10U-10-X-S4-SS: KAIROSNAME: C97
3C99 = 10U-10-X-S4-SS: KAIROSNAME: C99
3C100 = 0.1U-35-X-S2-MU: KAIROSNAME: C100
3C101 = 10U-10-X-S4-SS: KAIROSNAME: C101
3C102 = 0.1U-35-X-S2-MU: KAIROSNAME: C102
3C105 = 0.1U-35-X-S2-MU: KAIROSNAME: C105
3C106 = 10U-10-X-S4-SS: KAIROSNAME: C106
3C107 = 0.1U-35-X-S2-MU: KAIROSNAME: C107
3C108 = 0.1U-25-X-S4-TY: KAIROSNAME: C108
3C109 = 10U-10-X-S4-SS: KAIROSNAME: C109
3C110 = 10U-10-X-S4-SS: KAIROSNAME: C110
3C111 = 10U-10-X-S4-SS: KAIROSNAME: C111
3C112 = 0.1U-35-X-S2-MU: KAIROSNAME: C112
3C113 = 10U-25-X-S6-MU: KAIROSNAME: C113
3C116 = 22U-25-X-S8-MU: KAIROSNAME: C116
3C117 = 22U-25-X-S8-MU: KAIROSNAME: C117
3C118 = 10U-10-X-S4-SS: KAIROSNAME: C118
3C119 = 0.1U-35-X-S2-MU: KAIROSNAME: C119
3C120 = 47U-16-T-SC: KAIROSNAME: C120
3C121 = 10U-16-T-SA: KAIROSNAME: C121
3C122 = 10U-10-X-S4-SS: KAIROSNAME: C122
3C123 = 10U-10-X-S4-SS: KAIROSNAME: C123
3C124 = 0.1U-35-X-S2-MU: KAIROSNAME: C124
3C125 = 10U-10-X-S4-SS: KAIROSNAME: C125
3C126 = 0.1U-35-X-S2-MU: KAIROSNAME: C126
3C127 = 10U-10-X-S4-SS: KAIROSNAME: C127
3C128 = 0.1U-35-X-S2-MU: KAIROSNAME: C128
3C129 = 10U-10-X-S4-SS: KAIROSNAME: C129
3C130 = 0.1U-25-X-S4-TY: KAIROSNAME: C130
3C131 = 22U-10-T-SA: KAIROSNAME: C131
3C132 = 22U-10-T-SA: KAIROSNAME: C132
3C133 = 22U-10-T-SA: KAIROSNAME: C133
3C134 = 22U-10-T-SA: KAIROSNAME: C134
3C135 = 22U-10-T-SA: KAIROSNAME: C135
3C136 = 10U-10-X-S4-SS: KAIROSNAME: C136
3C137 = 0.1U-25-X-S4-TY: KAIROSNAME: C137
3C138 = 10U-10-X-S4-SS: KAIROSNAME: C138
3C139 = 22U-25-X-S8-MU: KAIROSNAME: C139
3C140 = 47U-16-T-SC: KAIROSNAME: C140
3C141 = 10U-16-T-SA: KAIROSNAME: C141
3C142 = 22U-25-X-S8-MU: KAIROSNAME: C142
3J5 = HDR-1X1-M: KAIROSNAME: J5
3J6 = HDR-2X1-M: KAIROSNAME: J6
3J7 = HDR-2X1-M: KAIROSNAME: J7
3J8 = HDR-2X1-M: KAIROSNAME: J8
3J9 = HDR-2X1-M: KAIROSNAME: J9
3K20 = CU_UA2-12NJ-A-V2: KAIROSNAME: K20
3K21 = CU_UA2-12NJ-A-V2: KAIROSNAME: K21
3K22 = CU_UA2-12NJ-A-V2: KAIROSNAME: K22
3K23 = CU_UA2-12NJ-A-V2: KAIROSNAME: K23
3K25 = CU_UA2-12NJ-A-V2: KAIROSNAME: K25
3K26 = CU_UA2-12NJ-A-V2: KAIROSNAME: K26
3K28 3K30-3K32 = CU_UA2-12NJ-A-V2: KAIROSNAME: K28
3K29 = CU_UA2-12NJ-A-V2: KAIROSNAME: K29
3L1 = L2.2U-1.15A-S2.0X1.6-TDK: KAIROSNAME: L1
3L3 = L2.2U-1.15A-S2.0X1.6-TDK: KAIROSNAME: L3
3L4 = L2.2U-1.15A-S2.0X1.6-TDK: KAIROSNAME: L4
3R48 = 0-5-S4: KAIROSNAME: R48
3R49 = 0-5-S4: KAIROSNAME: R49
3R50 = 0-5-S4: KAIROSNAME: R50
3R51 = 0-5-S4: KAIROSNAME: R51
3R53 = 0-5-S4: KAIROSNAME: R53
3R54 = 0-5-S4: KAIROSNAME: R54
3R55 = 0-5-S4: KAIROSNAME: R55
3R71-3R73 = 2-5-D-2
3R76-3R79 3R81-3R83 = 0-5-S4
3ST3 3ST13-3ST15 = SHORT: KAIROSNAME: ST3
3ST4 = SHORT: KAIROSNAME: ST4
3ST5 3ST16-3ST19 = SHORT: KAIROSNAME: ST5
3ST8 = SHORT: KAIROSNAME: ST8
3ST11 = SHORT: KAIROSNAME: ST11
3ST12 = SHORT: KAIROSNAME: ST12
S3_1V3 = TP03-D: KAIROSNAME: S0_TP_VD3
S3_GND1 = TP03-D: KAIROSNAME: S0_GND1
S3_GND2 = TP03-D: KAIROSNAME: S0_GND2
S3_GND3 = TP03-D: KAIROSNAME: S0_GND3
S3_GND4 = TP03-D: KAIROSNAME: S0_GND4
S3_VD33_ALL1 = TP03-D: KAIROSNAME: S0_VD33_ALL1
S3_VDD09 = TP03-D: KAIROSNAME: S0_VDD09
S3_VDD18_A = TP03-D: KAIROSNAME: S0_VDD18_A
S3_VDD18_D = TP03-D: KAIROSNAME: S0_VDD18_D

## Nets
AGND: 3BD34.2 3BD35.2 3C1.1 3C3.2 3C4.1 3C5.2 3C8.2 3C9.1 3C10.2 3C11.1 3C12.2 3C15.2 3C16.1 3C19.2 3D1.2(CATHODE_D2) 3D2.2(CATHODE_D2) 3D3.2(CATHODE_D2) 3SMP1.G1 3SMP1.G2 3SMP1.G3 3SMP1.G4 3SMP1.G5 3SMP1.G6 3SMP1.G7 3SMP1.G8 3SMP1.G9 3SMP2.G1 3SMP2.G2 3SMP2.G3 3SMP2.G4 3SMP2.G5 3SMP2.G6 3SMP2.G7 3SMP2.G8 3SMP2.G9 3SMP3.G1 3SMP3.G2 3SMP3.G3 3SMP3.G4 3SMP3.G5 3SMP3.G6 3SMP3.G7 3SMP3.G8 3SMP3.G9 3U1.2(GND) 3U2.2(GND) ; also on sheet 2 5 8 14 17 20 23
DGND: 3BD34.1 3BD35.1 3C17.1 3C18.1 3C20.2 3C21.2 3C22.2 3C23.1 3C24.2 3C25.1 3C38.1 3C39.2 3C40.1 3C41.2 3C44.2 3C45.2 3C46.2 3C47.2 3C48.2 3C49.2 3C52.2 3C53.2 3C54.2 3C55.2 3C56.2 3C57.2 3C58.2 3C59.2 3C60.2 3C61.2 3C62.2 3C63.2 3C64.2 3C65.2 3C66.2 3C67.2 3C68.2 3C69.2 3C70.2 3C71.2 3C72.2 3C73.2 3C74.2 3C75.2 3C76.2 3C77.2 3C78.2 3C79.2 3C83.2 3C84.2 3C85.2 3C88.2 3C89.2 3C90.2 3C91.2 3C92.2 3C93.2 3C94.2 3C95.2 3C96.2 3C97.2 3C98.2 3C99.2 3C100.2 3C101.2 3C102.2 3C105.2 3C106.2 3C107.2 3C108.2 3C109.2 3C110.2 3C111.2 3C112.2 3C113.1 3C116.2 3C117.2 3C118.2 3C119.2 3C120.2 3C121.2 3C122.2 3C123.2 3C124.2 3C125.2 3C126.2 3C127.2 3C128.2 3C129.2 3C130.2 3C131.2 3C132.2 3C133.2 3C134.2 3C135.2 3C136.2 3C137.2 3C138.2 3C139.2 3C140.2 3C141.2 3C142.2 3C143.1 3C144.1 3C145.1 3C146.1 3C147.1 3C148.1 3C149.1 3C150.1 3C152.2 3C153.2 3J1.2 3J2.2 3J3.2 3J4.8 3R18.1 3R22.2 3R23.2 3R25.2 3R26.2 3R33.1 3R42.2 3R43.2 3R49.2 3R51.2 3R54.2 3R62.2 3R71.2 3R72.2 3R73.2 3ST5.2 3ST16.2 3ST17.2 3ST18.2 3ST19.2 3U3.4(GND) 3Y1.2 3Y1.4 S3_GND1.1(TP) S3_GND2.1(TP) S3_GND3.1(TP) S3_GND4.1(TP) SITE3.4(GND_SPS_DCORE) SITE3.30(GND) SITE3.74(GND_SPS_MEM) SITE3.99(GND_SPS_AUD) SITE3.EP(EPAD) SITE3.G1 SITE3.G2 SITE3.G3 SITE3.G4 SITE3.G5 SITE3.G6 SITE3.G7 SITE3.G8 SITE3.G9 SITE3.G10 SITE3.G11 SITE3.G12 SITE3.G13 SITE3.G14 SITE3.G15 SITE3.G16 SITE3.G17 SITE3.G18 SITE3.G19 SITE3.G20 SITE3.G21 SITE3.G22 SITE3.G23 SITE3.G24 SITE3.G25 SITE3.G26 SITE3.G27 SITE3.G28 SITE3.G29 SITE3.G30 SITE3.G31 SITE3.G32 SITE3.G33 ; also on sheet 2 3 4 5 6 7 8 9 10 14 15 16 17 18 19 20 21 22 23 24 25 26 27 29 30 32 34 37 39
S3_1_AOUT_LN: 3K10.4 3R45.1 3R67.1 3R68.1
S3_1_AOUT_LP: 3K10.5 3R69.1 3R70.1 3R75.1
S3_1_AOUT_RN: 3K14.4 3R47.1 3R63.1 3R64.1
S3_1_AOUT_RP: 3K14.5 3R65.1 3R66.1 3R74.1
S3_1_SPI_CLK: 3R15.1 3U3.6(SCLK)
S3_1_SPI_CS: 3R10.2 3U3.1(CS#)
S3_1_SPI_DATA0: 3R17.1 3U3.5(SI/SIO0)
S3_1_SPI_DATA1: 3R11.2 3U3.2(SO/SIO1)
S3_1_SPI_DATA2: 3R14.2 3R16.2 3R18.2 3U3.3(WP#/SIO2)
S3_1_SPI_DATA3: 3R12.1 3R13.1 3U3.7(RST#/SIO3)
S3_1_VDD09: 3BD1.1 3BD2.1 3BD37.1 3C60.1 3R48.2 3R76.1 3R77.1 3R78.1 3R79.1 3ST13.2
S3_1_VDD18_A: 3K26.2 3K26.5 3R50.1 S3_1V3.1(TP)
S3_1_VDD18_D: 3C113.2 3R53.2 3R81.1 3R82.1 3R83.1 3ST15.1
S3_2_AOUT_LN: 3K12.4 3R68.2
S3_2_AOUT_LP: 3K12.5 3R69.2
S3_2_AOUT_RN: 3K15.4 3R64.2
S3_2_AOUT_RP: 3K15.5 3R65.2
S3_2_VDD18_A: 3BD16.1 3BD17.1 3BD19.1 3BD20.1 3C89.1 3R50.2
S3_ATX_VD0V9: 3C65.1 3C66.1 3K21.6 3ST3.2 ; also on sheet 27
S3_ATX_VD1V8: 3J7.1 3J8.1 3J9.1 ; also on sheet 27
S3_ATX_VD33: 3BD33.1 3C131.1 3C132.1 3C133.1 3C134.1 3C135.1 3J6.2 ; also on sheet 27
S3_AVCC_DRV: 3C75.1 3C110.1 3R55.2 3ST14.1 SITE3.53(AVCC_DRV)
S3_CHIP_EN_1: 3R34.2 3SW5.1
S3_DPS_F001: 3C120.1 3C121.1 3J9.2 3K29.6 3ST11.2
S3_DPS_F002: 3C92.1 3C93.1 3C94.1 3C95.1 3J8.2 3K26.6 3ST8.2
S3_DPS_F004: 3C140.1 3C141.1 3J7.2 3K20.6 3ST12.2
S3_DPS_F006: 3C68.1 3C69.1 3C70.1 3C71.1 3C72.1 3K23.3 3K23.6 3ST4.2 S3_VD33_ALL1.1(TP)
S3_DPS_GS001: 3ST19.1
S3_DPS_GS002: 3ST18.1
S3_DPS_GS003-1: 3ST16.1
S3_DPS_GS004: 3ST17.1
S3_DPS_GS006: 3ST5.1
S3_DPS_S001: 3ST11.1
S3_DPS_S002: 3ST8.1
S3_DPS_S003-1: 3ST3.1
S3_DPS_S004: 3ST12.1
S3_DPS_S006: 3ST4.1
S3_HSDM: 3K5.8 SITE3.79(HSDM)
S3_HSDP: 3K5.2 SITE3.78(HSDP)
S3_LPC_001: 3K36.7
S3_LPC_002: 3K36.2
S3_LPC_003: 3K11.2
S3_LPC_005: 3K14.2
S3_LPC_006: 3K18.4
S3_LPC_007: 3K1.4
S3_LPC_008: 3K35.2
S3_LPC_010: 3K34.7
S3_LPC_013+: 3K5.3 3K7.2
S3_LPC_013-: 3K5.7 3K7.8
S3_LPC_016: 3K2.5
S3_LPC_017: 3K35.7
S3_LPC_019: 3K12.2
S3_LPC_021: 3K1.5
S3_LPC_022: 3K15.2
S3_LPC_023: 3K3.4
S3_LPC_024: 3J4.2 3R35.1 SITE3.69(UART2_TXD/TEST_MODE_SEL/DMIC0_CLK/GPIOF_1/PB[22])
S3_LPC_025: 3J4.1 3R34.1 SITE3.71(CHIP_EN)
S3_LPC_026: 3K2.4
S3_LPC_027: 3K10.2
S3_LPC_028: 3K10.7
S3_LPC_029: 3K13.7
S3_LPC_030: 3K16.2
S3_LPC_032: 3K15.7
S3_LPC_033: 3K14.7
S3_LPC_034: 3K18.5
S3_LPC_035: 3K12.7
S3_LPC_036: 3K34.2
S3_LPC_038: 3K13.2
S3_LPC_039: 3K3.5
S3_LPC_040: 3K11.7
S3_LPC_041: 3J4.3 3R36.1 SITE3.68(UART2_RXD/BOOT_SEL/DMIC0_DATA/GPIOF_0/PB[21])
S3_LPC_042: 3C18.2 SITE3.50(MIC_BIAS2/GPIOC_13/PA[31])
S3_LPC_044: 3J4.5 3R39.1 SITE3.58(I2S3_DOUT1/DMIC_DATA2/ICFG1/GPIOD_4/PB[11])
S3_LPC_045: 3K39.3
S3_LPC_046: SITE3.67(I2S2_DIN3/I2S3_DOUT3/SPK_CLK/SPI0_CS/GPIOE_6/PB[20])
S3_LPC_047: 3J4.7 3R41.1 SITE3.18(GPIOB_7/PA[16]/ICFG3/SPI0_CS/UART0_RTS/HP_I2C2_SCL/ANT_SEL_N)
S3_LPC_048: 3K6.4
S3_LPC_049: SITE3.8(GPIOA_5/PA[5]/TOUCH5/ADC5/UART1_TXD/SPI1_MOSI/PWM4)
S3_LPC_050: SITE3.7(GPIOA_4/PA[4]/TOUCH4/ADC4/UART1_RXD/SPI1_MISO/PWM3/HP_I2C1_SCL)
S3_LPC_051: 3C17.2 SITE3.49(MIC_BIAS1/GPIOC_12/PA[30])
S3_LPC_052: 3C21.1 SITE3.48(AVCC)
S3_LPC_053: 3J4.4 3R37.1 SITE3.57(I2S3_DOUT0/DMIC_DATA1/ICFG0/BT_LOG/GPIOD_3/PB[10])
S3_LPC_054: 3K6.5
S3_LPC_055: SITE3.10(VBAT_MEAS)
S3_LPC_057: 3K9.4
S3_LPC_058: 3J4.6 3R40.1 SITE3.17(GPIOB_6/PA[15]/ICFG2/SPI0_CLK/UART0_CTS/HP_I2C2_SDA/ANT_SEL_P)
S3_LPC_059: 3K39.6
S3_LPC_060: SITE3.66(I2S2_DIN2/I2S3_DOUT2/SPK_DATA/SPI0_CK/GPIOE_5/PB[19])
S3_LPC_A_015: 3K8.4
S3_LPC_A_020: 3K8.5
S3_LPC_B_031: 3K4.4
S3_LPC_B_037: 3K4.5
S3_LX_AUD: 3K20.3 SITE3.100(LX_AUD)
S3_LX_AUD_CH_1: 3K20.4 ; also on sheet 10
S3_LX_AUD_CH_2: 3ST14.2 ; also on sheet 10
S3_LX_DCORE: 3K21.3 SITE3.3(LX_DCORE)
S3_LX_DCORE_CH: 3K21.4 ; also on sheet 10
S3_LX_MEM: 3K29.3 SITE3.75(LX_MEM)
S3_LX_MEM_CH_1: 3K29.4 ; also on sheet 10
S3_LX_MEM_CH_2: 3ST15.2 ; also on sheet 10
S3_MIPITX_CKN: 3K36.6 SITE3.82(MIPITX_CKN)
S3_MIPITX_CKP: 3K36.3 SITE3.83(MIPITX_CKP)
S3_MIPITX_DATAN_0: 3K34.6 SITE3.85(MIPITX_DATAN_0)
S3_MIPITX_DATAN_1: 3K35.6 SITE3.80(MIPITX_DATAN_1)
S3_MIPITX_DATAP_0: 3K34.3 SITE3.86(MIPITX_DATAP_0)
S3_MIPITX_DATAP_1: 3K35.3 SITE3.81(MIPITX_DATAP_1)
S3_PA2: 3K18.3 SITE3.5(GPIOA_2/PA[2]/TOUCH2/ADC2/UART0_RXD/SPI1_CS)
S3_PA3: 3K18.6 SITE3.6(GPIOA_3/PA[3]/TOUCH3/ADC3/UART0_TXD/SPI1_CLK/LEDC/HP_I2C1_SDA)
S3_PA9_CH: 3K39.2 SITE3.12(GPIOB_0/PA[9])
S3_PA10_CH: 3K39.7 SITE3.13(GPIOB_1/PA[10])
S3_PA13: 3K6.3 SITE3.15(GPIOB_4/PA[13]/SWD_DATA/SPI0_MOSI/UART0_RXD/HP_I2C1_SDA)
S3_PA13_UART_RX: 3K6.2 3R27.1
S3_PA13_UART_RX_1: 3J2.3 3R27.2
S3_PA14: 3K6.6 SITE3.16(GPIOB_5/PA[14]/SWD_CLK/SPI0_MISO/UART0_TXD/HP_I2C1_SCL)
S3_PA14_UART_TX: 3K6.7 3R28.1
S3_PA14_UART_TX_1: 3J2.4 3R28.2
S3_PA15_1: 3R40.2 3SW5.6
S3_PA16_1: 3R41.2 3SW5.7
S3_PA20: 3K15.6 SITE3.45(MIC1_P/GPIOC_2/PA[20])
S3_PA21: 3K15.3 SITE3.46(MIC1_N/GPIOC_3/PA[21])
S3_PA22: 3K11.6 SITE3.43(MIC2_P/GPIOC_4/PA[22])
S3_PA23: 3K11.3 SITE3.44(MIC2_N/GPIOC_5/PA[23])
S3_PA24: 3K12.6 SITE3.41(MIC3_P/I2C_SDA/GPIOC_6/PA[24])
S3_PA25: 3K12.3 SITE3.42(MIC3_N/I2C_SCL/GPIOC_7/PA[25])
S3_PA28: 3K13.6 SITE3.39(MIC5_P/ANT_SEL_P/GPIOC_10/PA[28])
S3_PA29: 3K13.3 SITE3.40(MIC5_N/ANT_SEL_N/GPIOC_11/PA[29])
S3_PB3: 3K10.6 SITE3.52(AOUT_LP/GPIOC_17/PB[3])
S3_PB3_AOUT_LP_2: 3K13.5 3R70.2
S3_PB4: 3K10.3 SITE3.51(AOUT_LN/GPIOC_18/PB[4])
S3_PB4_AOUT_LN_2: 3K13.4 3R67.2
S3_PB5: 3K14.6 SITE3.54(AOUT_RP/GPIOC_19/PB[5])
S3_PB5_AOUT_RP_2: 3K11.5 3R66.2
S3_PB6: 3K14.3 SITE3.55(AOUT_RN/GPIOC_20/PB[6])
S3_PB6_AOUT_RN_2: 3K11.4 3R63.2
S3_PB10_1: 3R37.2 3SW5.4
S3_PB11_1: 3R39.2 3SW5.5
S3_PB21_1: 3R36.2 3SW5.3
S3_PB22_1: 3R35.2 3SW5.2
S3_PB23: 3C144.2 3K4.3 3R57.1 SITE3.72(UART_LOG_RXD/OTP_BYPASS/GPIOF_2/PB[23])
S3_PB23_1: 3R57.2 3SW6.1
S3_PB23_SICK: 3K4.2 3R20.1
S3_PB23_SICK_1: 3J1.3 3R20.2
S3_PB24: 3C143.2 3K4.6 3R58.1 SITE3.73(UART_LOG_TXD/UART_DOWNLOAD/GPIOF_3/PB[24])
S3_PB24_1: 3R58.2 3SW6.2
S3_PB24_SIDD: 3K4.7 3R21.1
S3_PB24_SIDD_1: 3J1.4 3R21.2
S3_PB25: 3K8.3 3R59.1 SITE3.96(SPI0_CLK/SWD_CLK/SD_D2/ICFG2/GPIOG_0/PB[25])
S3_PB25_1: 3R59.2 3SW6.3
S3_PB25_I2C_SCL: 3K8.2 3R31.1
S3_PB25_I2C_SCL_1: 3J3.3 3R31.2
S3_PB26: 3K8.6 3R60.1 SITE3.97(SPI0_CS/SWD_DATA/SD_D3/ICFG3/GPIOG_1/PB[26])
S3_PB26_1: 3R60.2 3SW6.4
S3_PB26_I2C_SDA: 3K8.7 3R32.1
S3_PB26_I2C_SDA_1: 3J3.4 3R32.2
S3_RF_A: 3C13.1 3C14.1 3C15.1 3D3.1(CATHODE_D1) 3SMP3.1
S3_RF_G: 3C6.1 3C7.1 3C8.1 3D2.1(CATHODE_D1) 3SMP2.1
S3_RFIN_A: 3C16.2 3R9.1 SITE3.29(RFIN_A/GND_(<750um))
S3_RFIN_G: 3C9.2 3R5.1 SITE3.31(RFIN_G/GND)
S3_RFIO_A: 3C11.2 3R6.1 SITE3.28(RFIO_A__(<750um))
S3_RFIO_BT: 3C1.2 3R1.1 SITE3.37(RFIO_BT)
S3_RFIO_G: 3C4.2 3R2.1 SITE3.32(RFIO_G)
S3_RREF_MEM: 3K9.3 3R43.1 SITE3.60(RREF_MEM)
S3_SPI_CLK: 3K1.7 3R15.2
S3_SPI_CLK/PB28: 3K1.6 SITE3.90(SPI_FLASH_CLK/SD_CLK/GPIOG_3/PB[28])
S3_SPI_CS: 3K3.2 3R10.1
S3_SPI_CS/PC0: 3K3.3 SITE3.95(SPI_FLASH_CS/UART1_CTS/SD_CD/GPIOG_7/PC[0])
S3_SPI_D0/PB29: 3K1.3 SITE3.91(SPI_FLASH_DATA0/UART1_RXD/SD_D0/GPIOG_4/PB[29])
S3_SPI_D1/PB31: 3K3.6 SITE3.94(SPI_FLASH_DATA1/UART1_RTS/SD_WP/GPIOG_6/PB[31])
S3_SPI_D2/PB30: 3K2.6 SITE3.92(SPI_FLASH_DATA2/UART1_TXD/SD_D1/GPIOG_5/PB[30])
S3_SPI_D3/PB27: 3K2.3 SITE3.89(SPI_FLASH_DATA3/SD_CMD/GPIOG_2/PB[27])
S3_SPI_DATA0: 3K1.2 3R17.2
S3_SPI_DATA1: 3K3.7 3R11.1
S3_SPI_DATA2: 3K2.7 3R16.1
S3_SPI_DATA3: 3K2.2 3R13.2
S3_U1_VC1: 3K39.5 3U1.4(VCTL)
S3_U2_VC1: 3K39.4 3U2.4(VCTL)
S3_VA09_MIPI: 3BD37.2 3C152.1 SITE3.84(VA09_MIPI/VA09_CK/VA09_DA)
S3_VA09_PLL: 3BD1.2 3C44.1 SITE3.11(VA09_PLL/VD09_CORE0)
S3_VA09_USB: 3BD2.2 3C45.1 SITE3.77(VA09_USB)
S3_VA13_AFE: 3BD20.2 3C88.1 SITE3.19(VA13_AFE)
S3_VA13_SYN: 3BD16.2 3C78.1 SITE3.23(VR13_SYN)
S3_VA33_SYN: 3BD13.2 3C64.1 SITE3.24(VR33_SYN)
S3_VA33_XTAL: 3BD5.2 3C48.1 SITE3.20(VA33_XTAL)
S3_VD09_CORE1: 3C47.1 3R76.2 SITE3.56(VD09_CORE1/VD09MEM0)
S3_VD09_CORE2: 3C49.1 3R77.2 SITE3.64(VD09_CORE2/VD09_MEM1)
S3_VD09_CORE3: 3C54.1 3R78.2 SITE3.87(VD09_CORE3/VA09_PLL)
S3_VD09_CORE4: 3C58.1 3R79.2 SITE3.98(VD09_CORE4)
S3_VD13_FE: 3BD19.2 3C85.1 SITE3.36(VD13_FE)
S3_VD13_RF: 3BD17.2 3C79.1 SITE3.25(VD13_RF)
S3_VD33_ALL: 3BD3.1 3BD5.1 3BD7.1 3BD9.1 3BD11.1 3BD12.1 3BD13.1 3BD15.1 3BD18.1 3BD21.1 3BD22.1 3BD23.1 3BD28.1 3BD29.1 3BD30.1 3BD31.1 3BD32.1 3BD36.1 3C67.1 3C96.1 3C101.1 3C122.1 3C129.1 3J5.1 3J6.1 3K23.2 3K23.7
S3_VD33_CM_BT: 3BD21.2 3C90.1 3C91.1 SITE3.35(VD33_CM_BT)
S3_VD33_EX_FLASH: 3BD32.2 3C22.1 3C127.1 3C128.1 3R12.2 3R14.1 3U3.8(VCC)
S3_VD33_IO0: 3BD7.2 3C52.1 SITE3.9(VA33_PLL/VD33_IO0)
S3_VD33_IO2: 3BD9.2 3C56.1 SITE3.59(VD33_IO2/VD33_MEM)
S3_VD33_IO3: 3BD11.2 3C59.1 SITE3.70(VD33_IO3/VDD_IO4/VA33_USB)
S3_VD33_IO6: 3BD12.2 3C61.1 SITE3.88(VD33_IO6/VDD33_IO5/VD33_FLASH)
S3_VD33_SPS_AUD: 3BD30.2 3C123.1 3C124.1 SITE3.1(VD33_SPS_AUD)
S3_VD33_SPS_DCORE: 3BD28.2 3C111.1 3C112.1 SITE3.2(VD33_SPS_DCORE)
S3_VD33_SPS_MEM: 3BD31.2 3C125.1 3C126.1 SITE3.76(VD33_SPS_MEM)
S3_VD33PA_A: 3BD23.2 3C99.1 3C100.1 SITE3.27(VD33PA_A)
S3_VD33PA_BT: 3BD18.2 3C83.1 3C84.1 SITE3.38(VD33PA_BT)
S3_VD33PA_G: 3BD15.2 3C76.1 3C77.1 SITE3.33(VD33PA_G)
S3_VD33PAD_A: 3BD22.2 3C97.1 3C98.1 SITE3.26(VD33PAD_A)
S3_VD33PAD_G: 3BD36.2 3C73.1 3C74.1 SITE3.34(VD33PAD_G)
S3_VD1833_IO1: 3BD3.2 3C46.1 SITE3.14(VD1833_IO1)
S3_VD1833_SDIO: 3BD29.2 3C118.1 3C119.1 SITE3.93(VD1833_SDIO)
S3_VD_MEM0: 3C102.1 3R81.2 SITE3.61(VD_MEM0)
S3_VD_MEM1: 3C105.1 3R82.2 SITE3.62(VD_MEM1)
S3_VD_MEM2: 3C107.1 3R83.2 SITE3.65(VD_MEM2)
S3_VDD09: 3K22.2 3K22.5 3K31.4 3R48.1 S3_VDD09.1(TP)
S3_VDD09_CH: 3ST13.1 ; also on sheet 10
S3_VDD18_A: 3K25.2 3K25.5 3K26.3 3K32.4 3R55.1 S3_VDD18_A.1(TP)
S3_VDD18_D: 3K28.2 3K28.5 3K30.4 3R29.2 3R53.1 S3_VDD18_D.1(TP)
S3_VDD33: 3BD33.2 3C130.1 3R19.1 3R24.1 3R30.1 3R38.2 3R61.2 3U1.6(VDD) 3U2.6(VDD)
S3_VDD33_J1: 3J1.1 3R19.2
S3_VDD33_J2: 3J2.1 3R24.2
S3_VDD33_J3: 3J3.1 3R30.2
S3_VREF_DRAM: 3C153.1 3K16.3 SITE3.63(VREF_DRAM/NC(PSRAM))
S3_XI: 3C25.2 3Y1.1 SITE3.22(XI)
S3_XO: 3C23.2 3Y1.3 SITE3.21(XO)
S0123_CBIT_001: 3K7.9(V-) ; also on sheet 2 5 8
S0123_CBIT_003: 3K6.8(V-) ; also on sheet 2 5 8
S0123_CBIT_004: 3K2.8(V-) ; also on sheet 2 5 8
S0123_CBIT_005: 3K3.8(V-) ; also on sheet 2 5 8
S0123_CBIT_006: 3K35.8(V-) ; also on sheet 2 3 6 9
S0123_CBIT_008: 3K30.8(V-) ; also on sheet 2 4 7 10
S0123_CBIT_009: 3K32.8(V-) ; also on sheet 2 4 7 10
S0123_CBIT_010: 3K31.8(V-) ; also on sheet 2 4 7 10
S0123_CBIT_011: 3K29.8(V-) ; also on sheet 2 4 7 10
S0123_CBIT_012: 3K28.8(V-) ; also on sheet 2 4 7 10
S0123_CBIT_013: 3K8.8(V-) ; also on sheet 2 5 8
S0123_CBIT_014: 3K26.8(V-) ; also on sheet 2 4 7 10
S0123_CBIT_015: 3K34.8(V-) ; also on sheet 2 3 6 9
S0123_CBIT_016: 3K16.8(V-) ; also on sheet 2 5 8
S0123_CBIT_017: 3K21.8(V-) ; also on sheet 2 4 7 10
S0123_CBIT_018: 3K18.8(V-) ; also on sheet 2 3 6 9
S0123_CBIT_019: 3K22.8(V-) ; also on sheet 2 4 7 10
S0123_CBIT_020: 3K9.8(V-) ; also on sheet 2 5 8
S0123_CBIT_022: 3K19.8(V-) ; also on sheet 2 3 6 9
S0123_CBIT_023: 3K23.8(V-) ; also on sheet 2 4 7 10
S0123_CBIT_024: 3K20.8(V-) ; also on sheet 2 4 7 10
S0123_CBIT_025: 3K13.8(V-) ; also on sheet 2 3 6 9
S0123_CBIT_026: 3K14.8(V-) ; also on sheet 2 3 6 9
S0123_CBIT_027: 3K15.8(V-) ; also on sheet 2 3 6 9
S0123_CBIT_028: 3K25.8(V-) ; also on sheet 2 4 7 10
S0123_CBIT_029: 3K10.8(V-) ; also on sheet 2 3 6 9
S0123_CBIT_030: 3K11.8(V-) ; also on sheet 2 3 6 9
S0123_CBIT_031: 3K12.8(V-) ; also on sheet 2 3 6 9
S0123_CBIT_032: 3K39.8(V-) ; also on sheet 2 5 8
S0123_CBIT_033: 3K1.8(V-) ; also on sheet 2 5 8
S0123_CBIT_035: 3K5.9(V-) ; also on sheet 2 5 8
S0123_CBIT_036: 3K36.8(V-) ; also on sheet 2 3 6 9
S0123_CBIT_037: 3K4.8(V-) ; also on sheet 2 5 8
VP12: 3K1.1(V+) 3K2.1(V+) 3K3.1(V+) 3K4.1(V+) 3K5.1(V+) 3K6.1(V+) 3K7.1(V+) 3K8.1(V+) 3K9.1(V+) 3K10.1(V+) 3K11.1(V+) 3K12.1(V+) 3K13.1(V+) 3K14.1(V+) 3K15.1(V+) 3K16.1(V+) 3K18.1(V+) 3K19.1(V+) 3K20.1(V+) 3K21.1(V+) 3K22.1(V+) 3K23.1(V+) 3K25.1(V+) 3K26.1(V+) 3K28.1(V+) 3K29.1(V+) 3K30.1(V+) 3K31.1(V+) 3K32.1(V+) 3K34.1(V+) 3K35.1(V+) 3K36.1(V+) 3K39.1(V+) ; also on sheet 2 3 4 5 6 7 8 9 10 14 15 16 17 18 19 20 21 22 23 24 25 26 27 29 38
N27457514: 3C10.1 3R5.2 3U1.3(RF2)
N27457520: 3C7.2 3U1.5(ANT)
N27457523: 3R4.1 3U1.1(RF1)
N27457574: 3C6.2 3R3.2
N27457583: 3C19.1 3R9.2 3U2.1(RF1)
N27457590: 3C14.2 3U2.5(ANT)
N27457597: 3C12.1 3R6.2 3R7.1 3R8.2
N27457599: 3C13.2 3R7.2
N27457618: 3BD27.2 3C24.1 3K16.4
N27457628: 3K5.6 3R22.1
N27457630: 3K5.4 3R25.1
N27457633: 3R8.1 3U2.3(RF2)
N27457639: 3C5.1 3R2.2 3R3.1 3R4.2
N27457667: 3C2.1 3C3.1 3R1.2
N27457672: 3C2.2 3D1.1(CATHODE_D1) 3SMP1.1
N27457790: 3K7.6 3R23.1
N27457791: 3K7.4 3R26.1
N27457796: 3BD27.1 3R29.1 3R33.2
N27457923: 3C20.1 SITE3.47(VREF_AUDIO)
N27461522: 3K18.2 3K19.3
N27461523: 3K18.7 3K19.6
N27461526: 3C39.1 3K19.4
N27461527: 3C38.2 3K19.2
N27461530: 3C41.1 3K19.5
N27461531: 3C40.2 3K19.7
N27461562: 3R47.2 3R74.2
N27461644: 3R45.2 3R75.2
N27461660: 3C145.2 3K34.4
N27461661: 3C146.2 3K34.5
N27461668: 3C147.2 3K35.4
N27461669: 3C148.2 3K35.5
N27461672: 3C149.2 3K36.4
N27461673: 3C150.2 3K36.5
N27462760: 3K21.2 3L1.1
N27462790: 3K29.2 3L3.1
N27462791: 3C106.1 3C108.1 3C109.1 3K28.3 3L3.2
N27462802: 3K28.4 3R54.1
N27462806: 3C116.1 3C117.1 3K28.6 3K29.5
N27462829: 3C53.1 3C55.1 3C57.1 3K22.3 3L1.2
N27462841: 3K22.4 3R49.1
N27462845: 3C62.1 3C63.1 3K21.5 3K22.6
N27462960: 3K20.2 3L4.1
N27462961: 3C136.1 3C137.1 3C138.1 3K25.3 3L4.2
N27462972: 3K25.4 3R51.1
N27462974: 3C139.1 3C142.1 3K20.5 3K25.6
N27463080: 3K30.3 3R71.1
N27463082: 3K31.3 3R72.1
N27463084: 3K32.3 3R73.1
N27681031: 3R61.1 3SW6.6
N27681035: 3R62.1 3SW6.5
N27681115: 3R38.1 3SW5.10
N27681119: 3R42.1 3SW5.9

Not connected (* = marked no-connect by the designer): 3K7 3* 7*; 3K9 2* 5* 6* 7*; 3K16 5* 6* 7*; 3K20 7*; 3K21 7*; 3K22 7*; 3K23 4* 5*; 3K25 7*; 3K26 4* 7*; 3K28 7*; 3K29 7*; 3K30 2* 5* 6* 7*; 3K31 2* 5* 6* 7*; 3K32 2* 5* 6* 7*; 3SW5 8*; SITE3 GH1* GH2* GH3* GH4* NUT1* NUT2* NUT3* NUT4*

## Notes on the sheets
sheet 11
- WIFI/BT_RF
- place by Z-shape
- R3 and R4 Share PAD,
  Default R3
- C6 and C7 Share PAD,
  Default C6
- place by Z-shape
- place by Z-shape
- R7 and R8 Share PAD,
  Default R7
- C13 and C14 Share PAD,
  Default C13
- place by Z-shape
- place by Z-shape
- GND Shielding
- FLASH
- RF SW Channel  and PA9.10 share one Channel
- GND Shielding
- Mark On Board
- GND Shielding
- Debug
- 1.S0_VDD33
- 2.GND
- 3.S0_SICK
- DSSC
- 4.S0_SIDD
- SIC
- USB
- GND Shielding
- Mark On Board
- Debug
- 1.S0_VDD33
- 2.GND
- 3.S0_UART_RX
- 4.S0_UART_TX
- DIFF 90ohm
- UART
- DIFF 90ohm
- Debug
- Mark On Board
- XTAL
- VREF_DRAM
- GND Shielding
- 1.S0_VDD33
- Close To DUT
- 2.GND
- 3.S0_I2C_SCL
- DSSC
- 4.S0_I2C_SDA
- BT_I2C
- GND Shielding
- Mark On Board
- 1.S0_CHIP_EN
- 2.S0_PB22_TEST_MODE_SEL
- 3.S0_PB21_BOOT_SEL_FLASH
- 4.S0_PB10/ICFG0
- 5.S0_PB11/ICFG1
- 6.S0_PA15/ICFG2
- 7.S0_PA16/ICFG3
- 8.NC
- RREF
- Close To DUT
- Close to Relay
sheet 12
- AUDIO ADC Test
- MIPI Test
- GND Shielding
- GND Shielding
- CAP TOUCH Test
- GND Shielding
sheet 13
- CLOSE TO DUT
- POWER_VD09
- POWER_VD1833
- CLOSE TO DUT
- 110mA
- 5mA
- 33mA
- C48 TOP
- 20mA
- 102mA
- 35mA
- 105mA
- 35mA
- 112mA
- 25mA
- 50mA
- Mark On Board : S0_VDD09
- C58 TOP
- 30mA
- 50mA
- 10mA
- C64 TOP
- 200mA
- CLOSE TO DUT
- 200mA
- POWER_VD18_AUD
- CLOSE TO DUT
- Mark On Board : S0_VDD18_A
- 200mA
- 100mA
- C75 TOP
- 50mA
- Mark On Board : S0_VDD33
- CLOSE TO DUT
- CLOSE TO DUT
- 45mA
- 60mA
- C78 TOP
- 80mA
- C79 TOP
- 45mA
- C97,C98 TOP
- 300mA
- 25mA
- C88 TOP
- C99,C100 TOP
- POWER_VD18_DDR
- CLOSE TO DUT
- CLOSE TO DUT
- 155mA
- 62mA
- C111,C112 TOP
- 62mA
- 30mA
- 62mA
- Mark On Board : S0_VDD18_D
- C107 TOP
- 107mA
- C123,C124 TOP
- 160mA
- C125,C126 TOP
- 50mA
- Calibration Loading SCH
